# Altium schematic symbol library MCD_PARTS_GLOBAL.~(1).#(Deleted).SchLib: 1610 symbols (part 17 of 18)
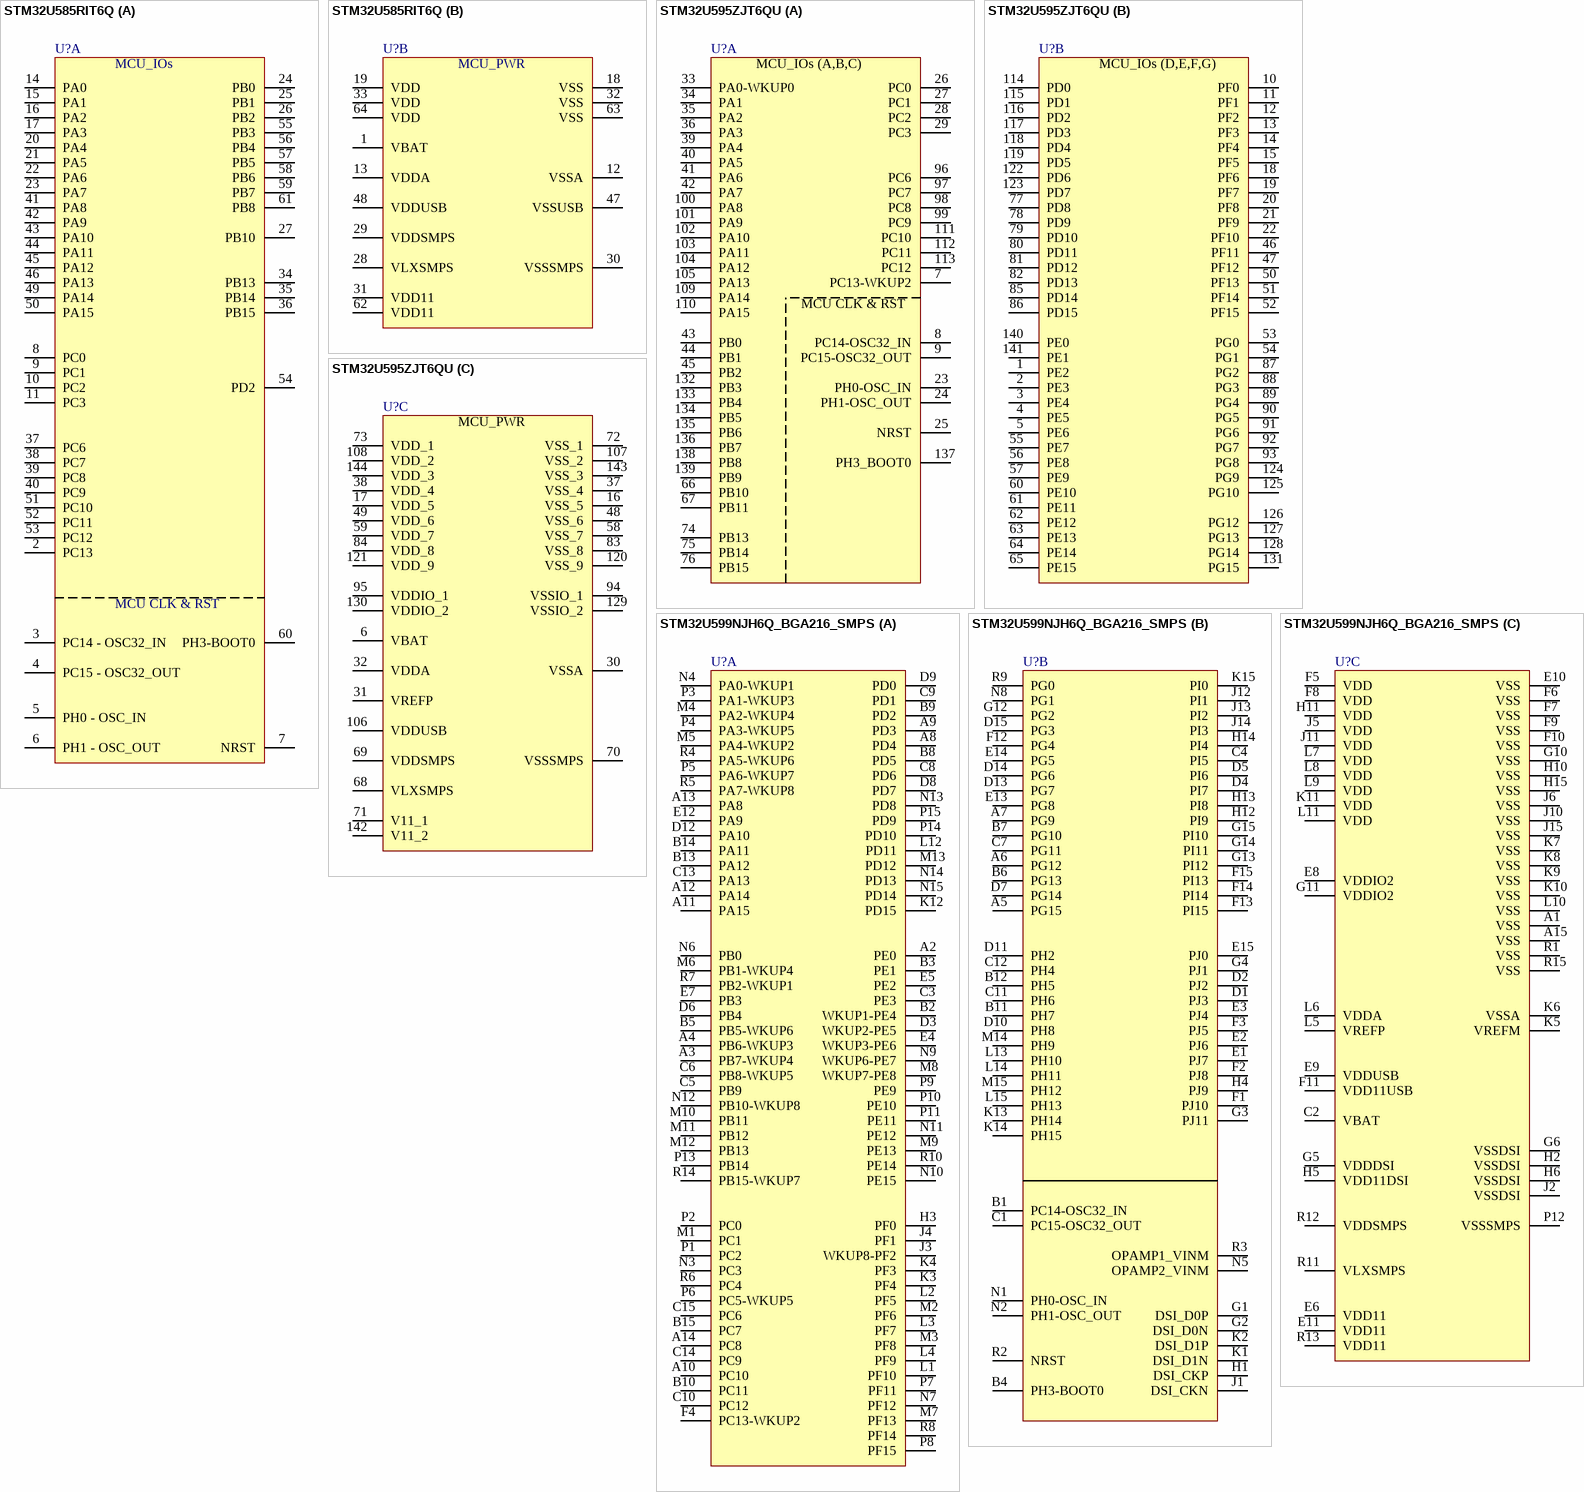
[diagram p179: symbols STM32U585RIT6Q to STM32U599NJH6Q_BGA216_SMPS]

## STM32U599NJH6Q_BGA216_SMPS
designator U?
part A pins: A2 PE0, A3 PB7-WKUP4, A4 PB6-WKUP3, A8 PD4, A9 PD3, A10 PC10, A11 PA15, A12 PA14, A13 PA8, A14 PC8, B2 WKUP1-PE4, B3 PE1, B5 PB5-WKUP6, B8 PD5, B9 PD2, B10 PC11, B13 PA12, B14 PA11, B15 PC7, C3 PE3, C5 PB9, C6 PB8-WKUP5, C8 PD6, C9 PD1, C10 PC12, C13 PA13, C14 PC9, C15 PC6, D3 WKUP2-PE5, D6 PB4, D8 PD7, D9 PD0, D12 PA10, E4 WKUP3-PE6, E5 PE2, E7 PB3, E12 PA9, F4 PC13-WKUP2, H3 PF0, J3 WKUP8-PF2, J4 PF1, K3 PF4, K4 PF3, K12 PD15, L1 PF10, L2 PF5, L3 PF7, L4 PF9, L12 PD11, M1 PC1, M2 PF6, M3 PF8, M4 PA2-WKUP4, M5 PA4-WKUP2, M6 PB1-WKUP4, M7 PF13, M8 WKUP7-PE8, M9 PE13, M10 PB11, M11 PB12, M12 PB13, M13 PD12, N3 PC3, N4 PA0-WKUP1, N6 PB0, N7 PF12, N9 WKUP6-PE7, N10 PE15, N11 PE12, N12 PB10-WKUP8, N13 PD8, N14 PD13, N15 PD14, P1 PC2, P2 PC0, P3 PA1-WKUP3, P4 PA3-WKUP5, P5 PA6-WKUP7, P6 PC5-WKUP5, P7 PF11, P8 PF15, P9 PE9, P10 PE10, P11 PE11, P13 PB14, P14 PD10, P15 PD9, R4 PA5-WKUP6, R5 PA7-WKUP8, R6 PC4, R7 PB2-WKUP1, R8 PF14, R10 PE14, R14 PB15-WKUP7
part B pins: A5 PG15, A6 PG12, A7 PG9, B1 PC14-OSC32_IN, B4 PH3-BOOT0, B6 PG13, B7 PG10, B11 PH7, B12 PH5, C1 PC15-OSC32_OUT, C4 PI5, C7 PG11, C11 PH6, C12 PH4, D1 PJ3, D2 PJ2, D4 PI7, D5 PI6, D7 PG14, D10 PH8, D11 PH2, D13 PG7, D14 PG6, D15 PG3, E1 PJ7, E2 PJ6, E3 PJ4, E13 PG8, E14 PG5, E15 PJ0, F1 PJ10, F2 PJ8, F3 PJ5, F12 PG4, F13 PI15, F14 PI14, F15 PI13, G1 DSI_D0P, G2 DSI_D0N, G3 PJ11, G4 PJ1, G12 PG2, G13 PI12, G14 PI11, G15 PI10, H1 DSI_CKP, H4 PJ9, H12 PI9, H13 PI8, H14 PI4, J1 DSI_CKN, J12 PI1, J13 PI2, J14 PI3, K1 DSI_D1N, K2 DSI_D1P, K13 PH14, K14 PH15, K15 PI0, L13 PH10, L14 PH11, L15 PH13, M14 PH9, M15 PH12, N1 PH0-OSC_IN, N2 PH1-OSC_OUT, N5 OPAMP2_VINM, N8 PG1, R2 NRST, R3 OPAMP1_VINM, R9 PG0
part C pins: A1 VSS, A15 VSS, C2 VBAT, E6 VDD11, E8 VDDIO2, E9 VDDUSB, E10 VSS, E11 VDD11, F5 VDD, F6 VSS, F7 VSS, F8 VDD, F9 VSS, F10 VSS, F11 VDD11USB, G5 VDDDSI, G6 VSSDSI, G10 VSS, G11 VDDIO2, H2 VSSDSI, H5 VDD11DSI, H6 VSSDSI, H10 VSS, H11 VDD, H15 VSS, J2 VSSDSI, J5 VDD, J6 VSS, J10 VSS, J11 VDD, J15 VSS, K5 VREFM, K6 VSSA, K7 VSS, K8 VSS, K9 VSS, K10 VSS, K11 VDD, L5 VREFP, L6 VDDA, L7 VDD, L8 VDD, L9 VDD, L10 VSS, L11 VDD, P12 VSSSMPS, R1 VSS, R11 VLXSMPS, R12 VDDSMPS, R13 VDD11, R15 VSS

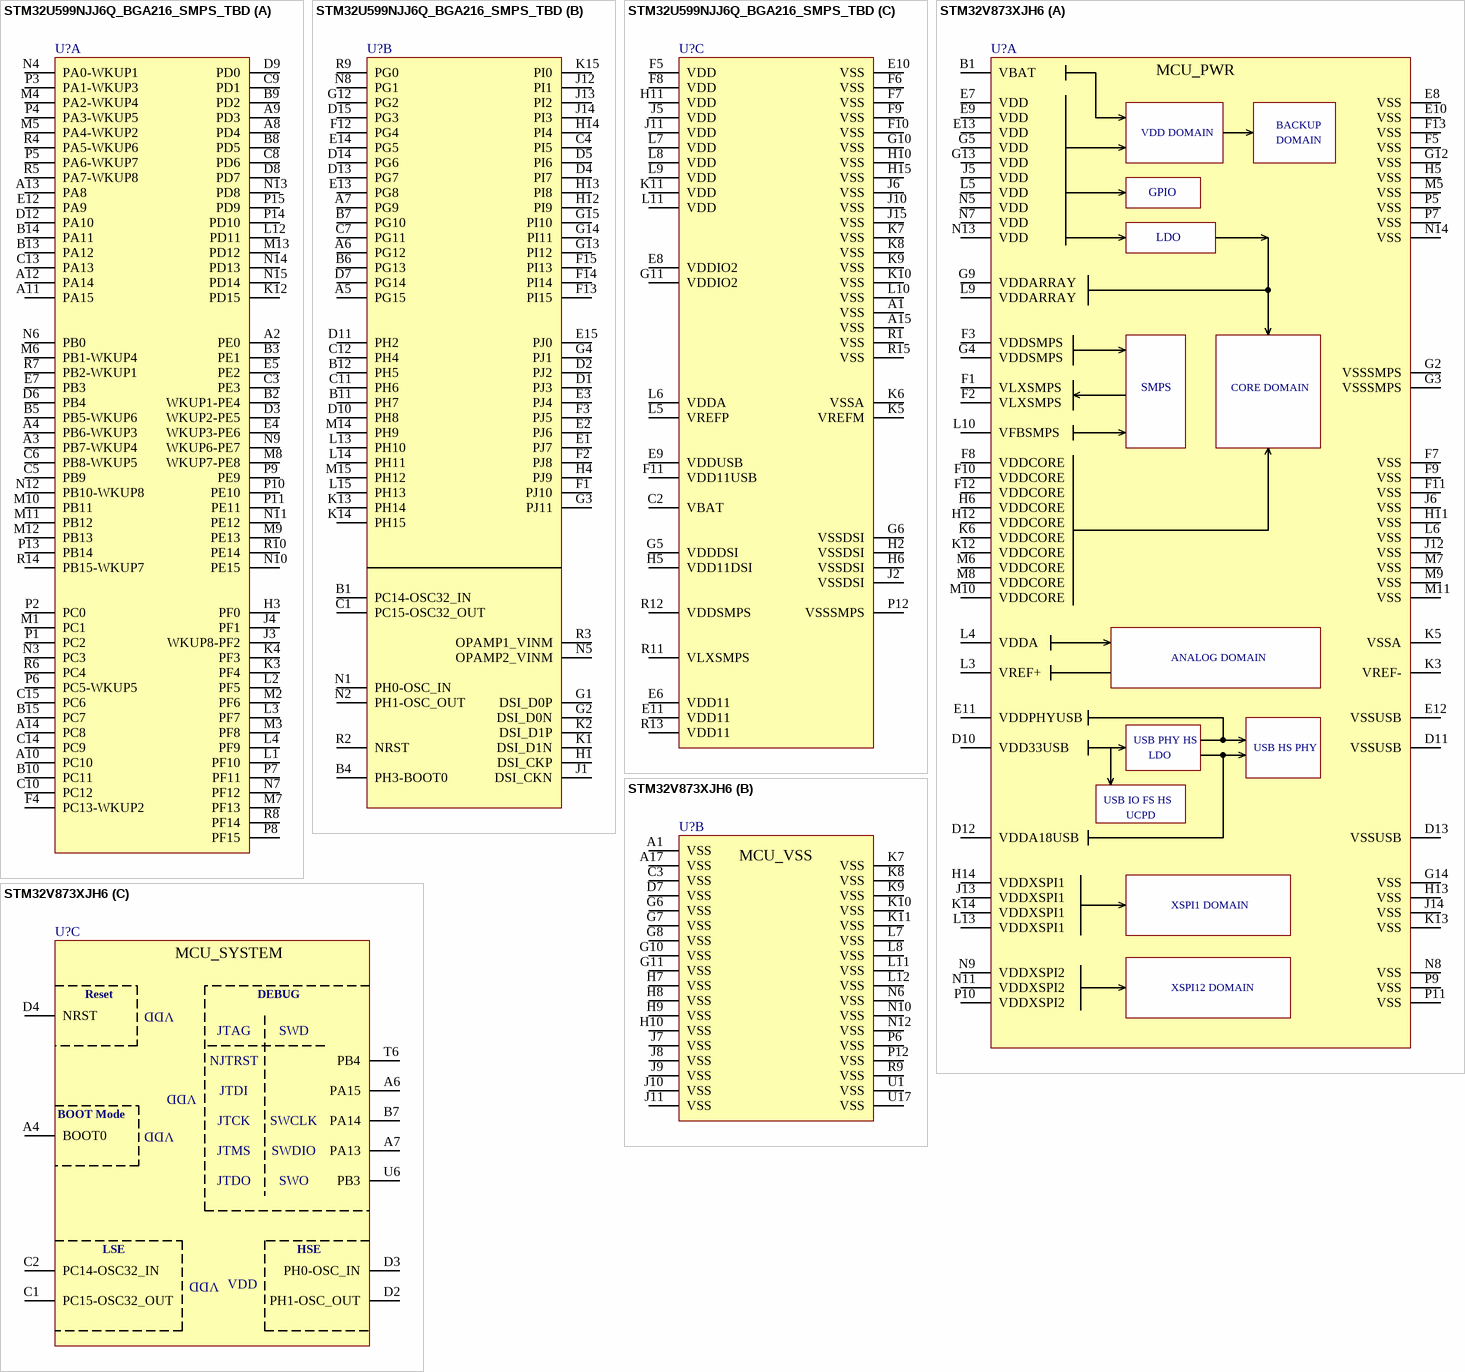
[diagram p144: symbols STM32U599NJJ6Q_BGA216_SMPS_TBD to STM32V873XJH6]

## STM32U599NJJ6Q_BGA216_SMPS_TBD
designator U?
part A pins: A2 PE0, A3 PB7-WKUP4, A4 PB6-WKUP3, A8 PD4, A9 PD3, A10 PC10, A11 PA15, A12 PA14, A13 PA8, A14 PC8, B2 WKUP1-PE4, B3 PE1, B5 PB5-WKUP6, B8 PD5, B9 PD2, B10 PC11, B13 PA12, B14 PA11, B15 PC7, C3 PE3, C5 PB9, C6 PB8-WKUP5, C8 PD6, C9 PD1, C10 PC12, C13 PA13, C14 PC9, C15 PC6, D3 WKUP2-PE5, D6 PB4, D8 PD7, D9 PD0, D12 PA10, E4 WKUP3-PE6, E5 PE2, E7 PB3, E12 PA9, F4 PC13-WKUP2, H3 PF0, J3 WKUP8-PF2, J4 PF1, K3 PF4, K4 PF3, K12 PD15, L1 PF10, L2 PF5, L3 PF7, L4 PF9, L12 PD11, M1 PC1, M2 PF6, M3 PF8, M4 PA2-WKUP4, M5 PA4-WKUP2, M6 PB1-WKUP4, M7 PF13, M8 WKUP7-PE8, M9 PE13, M10 PB11, M11 PB12, M12 PB13, M13 PD12, N3 PC3, N4 PA0-WKUP1, N6 PB0, N7 PF12, N9 WKUP6-PE7, N10 PE15, N11 PE12, N12 PB10-WKUP8, N13 PD8, N14 PD13, N15 PD14, P1 PC2, P2 PC0, P3 PA1-WKUP3, P4 PA3-WKUP5, P5 PA6-WKUP7, P6 PC5-WKUP5, P7 PF11, P8 PF15, P9 PE9, P10 PE10, P11 PE11, P13 PB14, P14 PD10, P15 PD9, R4 PA5-WKUP6, R5 PA7-WKUP8, R6 PC4, R7 PB2-WKUP1, R8 PF14, R10 PE14, R14 PB15-WKUP7
part B pins: A5 PG15, A6 PG12, A7 PG9, B1 PC14-OSC32_IN, B4 PH3-BOOT0, B6 PG13, B7 PG10, B11 PH7, B12 PH5, C1 PC15-OSC32_OUT, C4 PI5, C7 PG11, C11 PH6, C12 PH4, D1 PJ3, D2 PJ2, D4 PI7, D5 PI6, D7 PG14, D10 PH8, D11 PH2, D13 PG7, D14 PG6, D15 PG3, E1 PJ7, E2 PJ6, E3 PJ4, E13 PG8, E14 PG5, E15 PJ0, F1 PJ10, F2 PJ8, F3 PJ5, F12 PG4, F13 PI15, F14 PI14, F15 PI13, G1 DSI_D0P, G2 DSI_D0N, G3 PJ11, G4 PJ1, G12 PG2, G13 PI12, G14 PI11, G15 PI10, H1 DSI_CKP, H4 PJ9, H12 PI9, H13 PI8, H14 PI4, J1 DSI_CKN, J12 PI1, J13 PI2, J14 PI3, K1 DSI_D1N, K2 DSI_D1P, K13 PH14, K14 PH15, K15 PI0, L13 PH10, L14 PH11, L15 PH13, M14 PH9, M15 PH12, N1 PH0-OSC_IN, N2 PH1-OSC_OUT, N5 OPAMP2_VINM, N8 PG1, R2 NRST, R3 OPAMP1_VINM, R9 PG0
part C pins: A1 VSS, A15 VSS, C2 VBAT, E6 VDD11, E8 VDDIO2, E9 VDDUSB, E10 VSS, E11 VDD11, F5 VDD, F6 VSS, F7 VSS, F8 VDD, F9 VSS, F10 VSS, F11 VDD11USB, G5 VDDDSI, G6 VSSDSI, G10 VSS, G11 VDDIO2, H2 VSSDSI, H5 VDD11DSI, H6 VSSDSI, H10 VSS, H11 VDD, H15 VSS, J2 VSSDSI, J5 VDD, J6 VSS, J10 VSS, J11 VDD, J15 VSS, K5 VREFM, K6 VSSA, K7 VSS, K8 VSS, K9 VSS, K10 VSS, K11 VDD, L5 VREFP, L6 VDDA, L7 VDD, L8 VDD, L9 VDD, L10 VSS, L11 VDD, P12 VSSSMPS, R1 VSS, R11 VLXSMPS, R12 VDDSMPS, R13 VDD11, R15 VSS

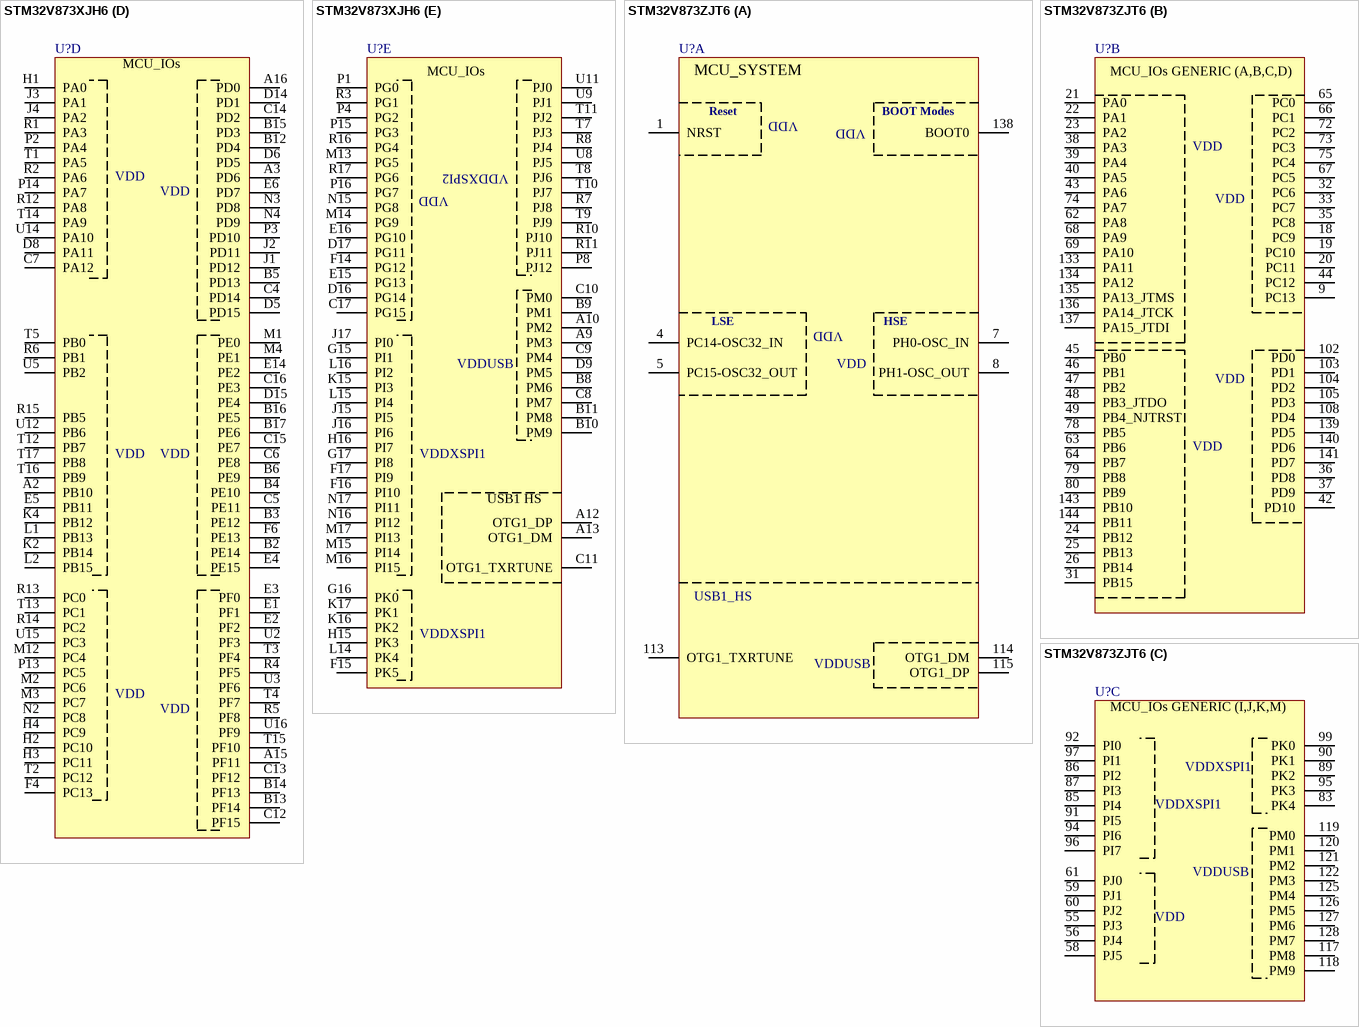
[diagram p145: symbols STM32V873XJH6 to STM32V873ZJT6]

## STM32V873XJH6
designator U?
part A pins: B1 VBAT, D10 VDD33USB, D11 VSSUSB, D12 VDDA18USB, D13 VSSUSB, E7 VDD, E8 VSS, E9 VDD, E10 VSS, E11 VDDPHYUSB, E12 VSSUSB, E13 VDD, F1 VLXSMPS, F2 VLXSMPS, F3 VDDSMPS, F5 VSS, F7 VSS, F8 VDDCORE, F9 VSS, F10 VDDCORE, F11 VSS, F12 VDDCORE, F13 VSS, G2 VSSSMPS, G3 VSSSMPS, G4 VDDSMPS, G5 VDD, G9 VDDARRAY, G12 VSS, G13 VDD, G14 VSS, H5 VSS, H6 VDDCORE, H11 VSS, H12 VDDCORE, H13 VSS, H14 VDDXSPI1, J5 VDD, J6 VSS, J12 VSS, J13 VDDXSPI1, J14 VSS, K3 VREF-, K5 VSSA, K6 VDDCORE, K12 VDDCORE, K13 VSS, K14 VDDXSPI1, L3 VREF+, L4 VDDA, L5 VDD, L6 VSS, L9 VDDARRAY, L10 VFBSMPS, L13 VDDXSPI1, M5 VSS, M6 VDDCORE, M7 VSS, M8 VDDCORE, M9 VSS, M10 VDDCORE, M11 VSS, N5 VDD, N7 VDD, N8 VSS, N9 VDDXSPI2, N11 VDDXSPI2, N13 VDD, N14 VSS, P5 VSS, P7 VSS, P9 VSS, P10 VDDXSPI2, P11 VSS
part B pins: A1 VSS, A17 VSS, C3 VSS, D7 VSS, G6 VSS, G7 VSS, G8 VSS, G10 VSS, G11 VSS, H7 VSS, H8 VSS, H9 VSS, H10 VSS, J7 VSS, J8 VSS, J9 VSS, J10 VSS, J11 VSS, K7 VSS, K8 VSS, K9 VSS, K10 VSS, K11 VSS, L7 VSS, L8 VSS, L11 VSS, L12 VSS, N6 VSS, N10 VSS, N12 VSS, P6 VSS, P12 VSS, R9 VSS, U1 VSS, U17 VSS
part C pins: A4 BOOT0, A6 PA15, A7 PA13, B7 PA14, C1 PC15-OSC32_OUT, C2 PC14-OSC32_IN, D2 PH1-OSC_OUT, D3 PH0-OSC_IN, D4 NRST, T6 PB4, U6 PB3
part D pins: A2 PB10, A3 PD6, A15 PF11, A16 PD0, B2 PE14, B3 PE12, B4 PE10, B5 PD13, B6 PE9, B12 PD4, B13 PF14, B14 PF13, B15 PD3, B16 PE5, B17 PE6, C4 PD14, C5 PE11, C6 PE8, C7 PA12, C12 PF15, C13 PF12, C14 PD2, C15 PE7, C16 PE3, D5 PD15, D6 PD5, D8 PA11, D14 PD1, D15 PE4, E1 PF1, E2 PF2, E3 PF0, E4 PE15, E5 PB11, E6 PD7, E14 PE2, F4 PC13, F6 PE13, H1 PA0, H2 PC10, H3 PC11, H4 PC9, J1 PD12, J2 PD11, J3 PA1, J4 PA2, K2 PB14, K4 PB12, L1 PB13, L2 PB15, M1 PE0, M2 PC6, M3 PC7, M4 PE1, M12 PC4, N2 PC8, N3 PD8, N4 PD9, P2 PA4, P3 PD10, P13 PC5, P14 PA7, R1 PA3, R2 PA6, R4 PF5, R5 PF8, R6 PB1, R12 PA8, R13 PC0, R14 PC2, R15 PB5, T1 PA5, T2 PC12, T3 PF4, T4 PF7, T5 PB0, T12 PB7, T13 PC1, T14 PA9, T15 PF10, T16 PB9, T17 PB8, U2 PF3, U3 PF6, U5 PB2, U12 PB6, U14 PA10, U15 PC3, U16 PF9
part E pins: A9 PM3, A10 PM2, A12 OTG1_DP, A13 OTG1_DM, B8 PM6, B9 PM1, B10 PM9, B11 PM8, C8 PM7, C9 PM4, C10 PM0, C11 OTG1_TXRTUNE, C17 PG15, D9 PM5, D16 PG14, D17 PG11, E15 PG13, E16 PG10, F14 PG12, F15 PK5, F16 PI10, F17 PI9, G15 PI1, G16 PK0, G17 PI8, H15 PK3, H16 PI7, J15 PI5, J16 PI6, J17 PI0, K15 PI3, K16 PK2, K17 PK1, L14 PK4, L15 PI4, L16 PI2, M13 PG5, M14 PG9, M15 PI14, M16 PI15, M17 PI13, N15 PG8, N16 PI12, N17 PI11, P1 PG0, P4 PG2, P8 PJ12, P15 PG3, P16 PG7, R3 PG1, R7 PJ8, R8 PJ4, R10 PJ10, R11 PJ11, R16 PG4, R17 PG6, T7 PJ3, T8 PJ6, T9 PJ9, T10 PJ7, T11 PJ2, U8 PJ5, U9 PJ1, U11 PJ0
1 alternate drawing of the same symbol

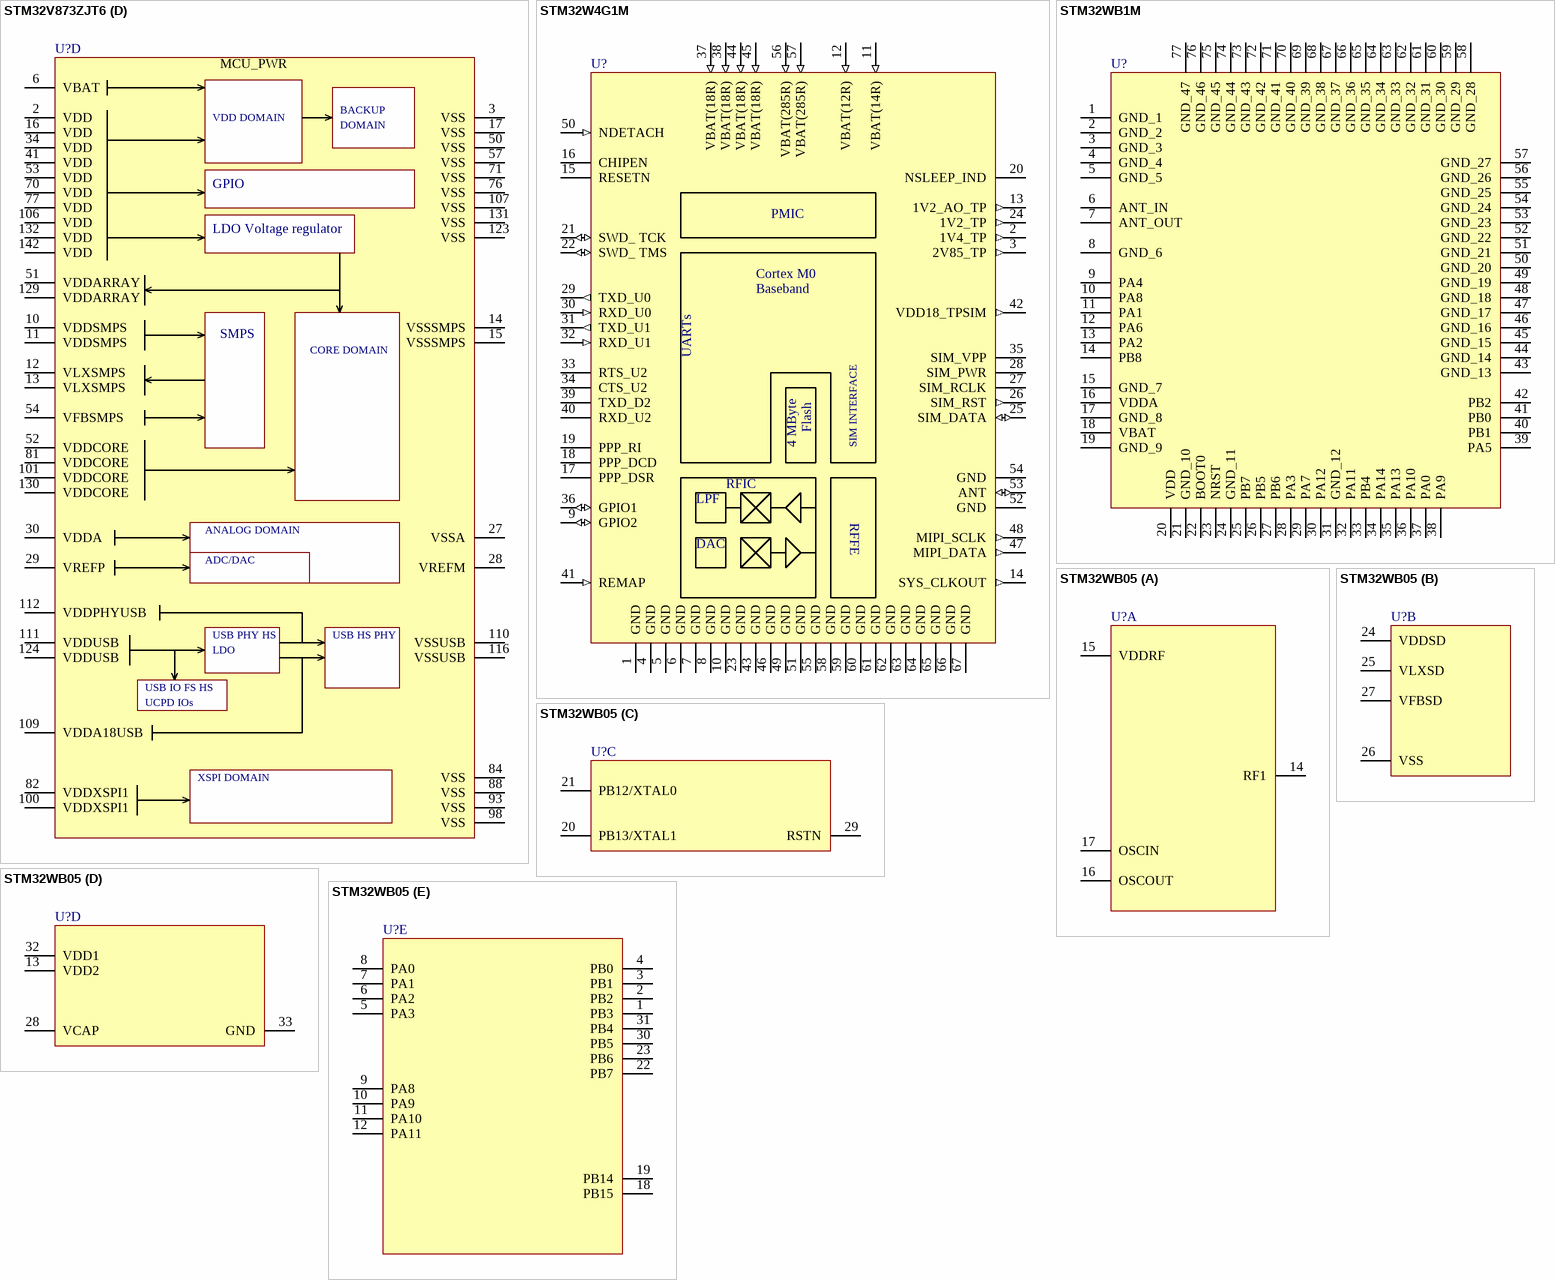
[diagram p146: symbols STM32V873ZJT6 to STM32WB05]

## STM32V873ZJT6
designator U?
part A pins: 1 NRST, 4 PC14-OSC32_IN, 5 PC15-OSC32_OUT, 7 PH0-OSC_IN, 8 PH1-OSC_OUT, 113 OTG1_TXRTUNE, 114 OTG1_DM, 115 OTG1_DP, 138 BOOT0
part B pins: 9 PC13, 18 PC9, 19 PC10, 20 PC11, 21 PA0, 22 PA1, 23 PA2, 24 PB12, 25 PB13, 26 PB14, 31 PB15, 32 PC6, 33 PC7, 35 PC8, 36 PD8, 37 PD9, 38 PA3, 39 PA4, 40 PA5, 42 PD10, 43 PA6, 44 PC12, 45 PB0, 46 PB1, 47 PB2, 48 PB3_JTDO, 49 PB4_NJTRST, 62 PA8, 63 PB6, 64 PB7, 65 PC0, 66 PC1, 67 PC5, 68 PA9, 69 PA10, 72 PC2, 73 PC3, 74 PA7, 75 PC4, 78 PB5, 79 PB8, 80 PB9, 102 PD0, 103 PD1, 104 PD2, 105 PD3, 108 PD4, 133 PA11, 134 PA12, 135 PA13_JTMS, 136 PA14_JTCK, 137 PA15_JTDI, 139 PD5, 140 PD6, 141 PD7, 143 PB10, 144 PB11
part C pins: 55 PJ3, 56 PJ4, 58 PJ5, 59 PJ1, 60 PJ2, 61 PJ0, 83 PK4, 85 PI4, 86 PI2, 87 PI3, 89 PK2, 90 PK1, 91 PI5, 92 PI0, 94 PI6, 95 PK3, 96 PI7, 97 PI1, 99 PK0, 117 PM8, 118 PM9, 119 PM0, 120 PM1, 121 PM2, 122 PM3, 125 PM4, 126 PM5, 127 PM6, 128 PM7
part D pins: 2 VDD, 3 VSS, 6 VBAT, 10 VDDSMPS, 11 VDDSMPS, 12 VLXSMPS, 13 VLXSMPS, 14 VSSSMPS, 15 VSSSMPS, 16 VDD, 17 VSS, 27 VSSA, 28 VREFM, 29 VREFP, 30 VDDA, 34 VDD, 41 VDD, 50 VSS, 51 VDDARRAY, 52 VDDCORE, 53 VDD, 54 VFBSMPS, 57 VSS, 70 VDD, 71 VSS, 76 VSS, 77 VDD, 81 VDDCORE, 82 VDDXSPI1, 84 VSS, 88 VSS, 93 VSS, 98 VSS, 100 VDDXSPI1, 101 VDDCORE, 106 VDD, 107 VSS, 109 VDDA18USB, 110 VSSUSB, 111 VDDUSB, 112 VDDPHYUSB, 116 VSSUSB, 123 VSS, 124 VDDUSB, 129 VDDARRAY, 130 VDDCORE, 131 VSS, 132 VDD, 142 VDD

## STM32W4G1M
designator U?
pins: 1 GND, 2 1V4_TP (out), 3 2V85_TP (out), 4 GND, 5 GND, 6 GND, 7 GND, 8 GND, 9 GPIO2 (io), 10 GND, 11 VBAT(14R) (in), 12 VBAT(12R) (in), 13 1V2_AO_TP (out), 14 SYS_CLKOUT (out), 15 RESETN, 16 CHIPEN, 17 PPP_DSR, 18 PPP_DCD, 19 PPP_RI, 20 NSLEEP_IND, 21 SWD_ TCK (io), 22 SWD_ TMS (io), 23 GND, 24 1V2_TP (out), 25 SIM_DATA (io), 26 SIM_RST (out), 27 SIM_RCLK, 28 SIM_PWR, 29 TXD_U0 (out), 30 RXD_U0 (in), 31 TXD_U1 (out), 32 RXD_U1 (in), 33 RTS_U2, 34 CTS_U2, 35 SIM_VPP, 36 GPIO1 (io), 37 VBAT(18R) (in), 38 VBAT(18R) (in), 39 TXD_D2, 40 RXD_U2, 41 REMAP (in), 42 VDD18_TPSIM (out), 43 GND, 44 VBAT(18R) (in), 45 VBAT(18R) (in), 46 GND, 47 MIPI_DATA (out), 48 MIPI_SCLK (out), 49 GND, 50 NDETACH (in), 51 GND, 52 GND (power), 53 ANT (io) "Antenna connector", 54 GND (power), 55 GND, 56 VBAT(285R) (in), 57 VBAT(285R) (in), 58 GND, 59 GND, 60 GND, 61 GND, 62 GND, 63 GND, 64 GND, 65 GND, 66 GND, 67 GND

## STM32WB1M
designator U?
pins: 1 GND_1, 2 GND_2, 3 GND_3, 4 GND_4, 5 GND_5, 6 ANT_IN, 7 ANT_OUT, 8 GND_6, 9 PA4, 10 PA8, 11 PA1, 12 PA6, 13 PA2, 14 PB8, 15 GND_7, 16 VDDA, 17 GND_8, 18 VBAT, 19 GND_9, 20 VDD, 21 GND_10, 22 BOOT0, 23 NRST, 24 GND_11, 25 PB7, 26 PB5, 27 PB6, 28 PA3, 29 PA7, 30 PA12, 31 GND_12, 32 PA11, 33 PB4, 34 PA14, 35 PA13, 36 PA10, 37 PA0, 38 PA9, 39 PA5, 40 PB1, 41 PB0, 42 PB2, 43 GND_13, 44 GND_14, 45 GND_15, 46 GND_16, 47 GND_17, 48 GND_18, 49 GND_19, 50 GND_20, 51 GND_21, 52 GND_22, 53 GND_23, 54 GND_24, 55 GND_25, 56 GND_26, 57 GND_27, 58 GND_28, 59 GND_29, 60 GND_30, 61 GND_31, 62 GND_32, 63 GND_33, 64 GND_34, 65 GND_35, 66 GND_36, 67 GND_37, 68 GND_38, 69 GND_39, 70 GND_40, 71 GND_41, 72 GND_42, 73 GND_43, 74 GND_44, 75 GND_45, 76 GND_46, 77 GND_47

## STM32WB05
designator U?
part A pins: 14 RF1, 15 VDDRF, 16 OSCOUT, 17 OSCIN
part B pins: 24 VDDSD, 25 VLXSD, 26 VSS, 27 VFBSD
part C pins: 20 PB13/XTAL1, 21 PB12/XTAL0, 29 RSTN
part D pins: 13 VDD2, 28 VCAP, 32 VDD1, 33 GND
part E pins: 1 PB3, 2 PB2, 3 PB1, 4 PB0, 5 PA3, 6 PA2, 7 PA1, 8 PA0, 9 PA8, 10 PA9, 11 PA10, 12 PA11, 18 PB15, 19 PB14, 22 PB7, 23 PB6, 30 PB5, 31 PB4

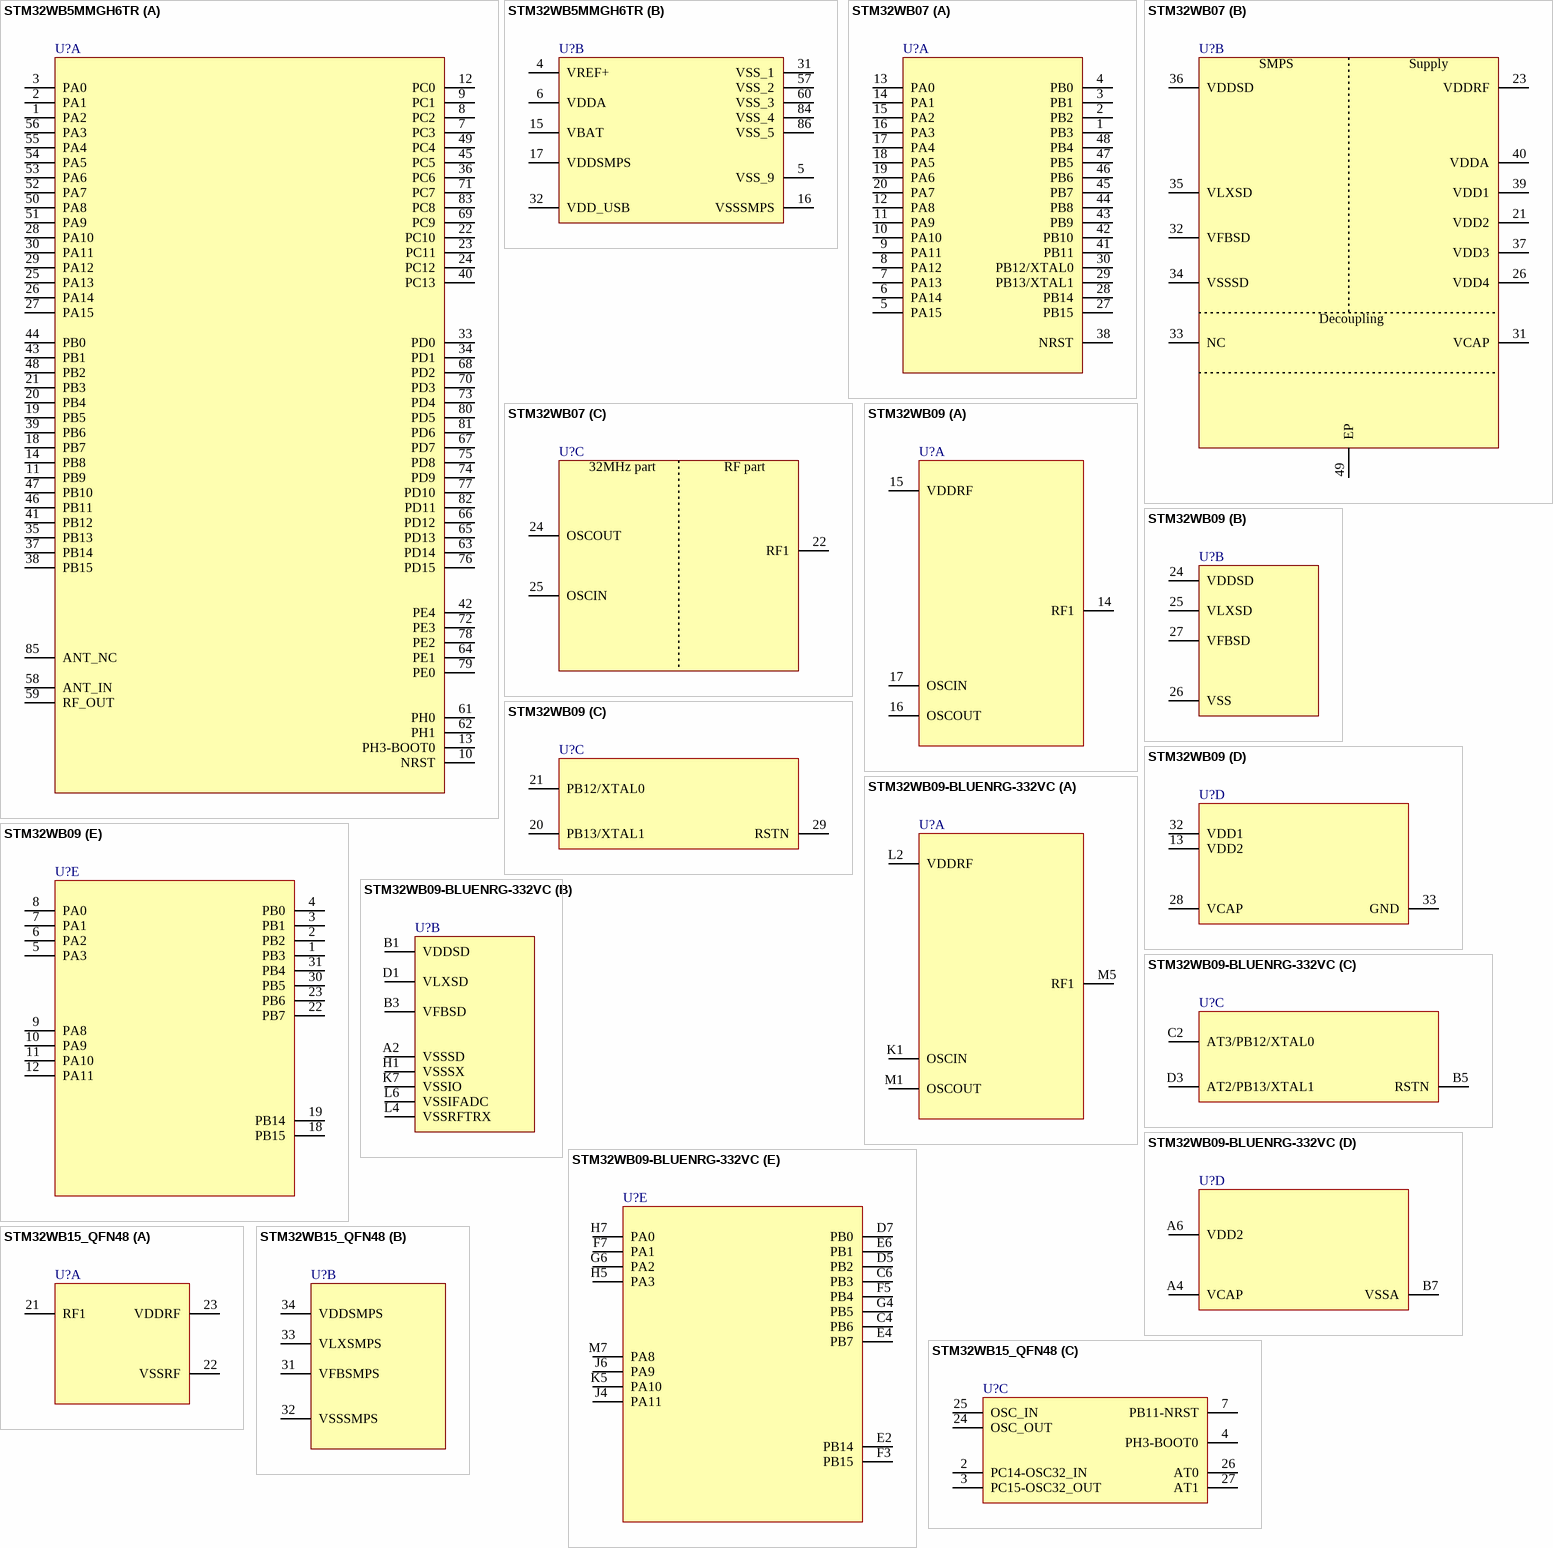
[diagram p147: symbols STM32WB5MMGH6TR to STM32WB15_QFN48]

## STM32WB5MMGH6TR
designator U?
part A pins: 1 PA2, 2 PA1, 3 PA0, 7 PC3, 8 PC2, 9 PC1, 10 NRST, 11 PB9, 12 PC0, 13 PH3-BOOT0, 14 PB8, 18 PB7, 19 PB5, 20 PB4, 21 PB3, 22 PC10, 23 PC11, 24 PC12, 25 PA13, 26 PA14, 27 PA15, 28 PA10, 29 PA12, 30 PA11, 33 PD0, 34 PD1, 35 PB13, 36 PC6, 37 PB14, 38 PB15, 39 PB6, 40 PC13, 41 PB12, 42 PE4, 43 PB1, 44 PB0, 45 PC5, 46 PB11, 47 PB10, 48 PB2, 49 PC4, 50 PA8, 51 PA9, 52 PA7, 53 PA6, 54 PA5, 55 PA4, 56 PA3, 58 ANT_IN, 59 RF_OUT, 61 PH0, 62 PH1, 63 PD14, 64 PE1, 65 PD13, 66 PD12, 67 PD7, 68 PD2, 69 PC9, 70 PD3, 71 PC7, 72 PE3, 73 PD4, 74 PD9, 75 PD8, 76 PD15, 77 PD10, 78 PE2, 79 PE0, 80 PD5, 81 PD6, 82 PD11, 83 PC8, 85 ANT_NC
part B pins: 4 VREF+, 5 VSS_9, 6 VDDA, 15 VBAT, 16 VSSSMPS, 17 VDDSMPS, 31 VSS_1, 32 VDD_USB, 57 VSS_2, 60 VSS_3, 84 VSS_4, 86 VSS_5

## STM32WB07
designator U?
part A pins: 1 PB3, 2 PB2, 3 PB1, 4 PB0, 5 PA15, 6 PA14, 7 PA13, 8 PA12, 9 PA11, 10 PA10, 11 PA9, 12 PA8, 13 PA0, 14 PA1, 15 PA2, 16 PA3, 17 PA4, 18 PA5, 19 PA6, 20 PA7, 27 PB15, 28 PB14, 29 PB13/XTAL1, 30 PB12/XTAL0, 38 NRST, 41 PB11, 42 PB10, 43 PB9, 44 PB8, 45 PB7, 46 PB6, 47 PB5, 48 PB4
part B pins: 21 VDD2, 23 VDDRF, 26 VDD4, 31 VCAP, 32 VFBSD, 33 NC, 34 VSSSD, 35 VLXSD, 36 VDDSD, 37 VDD3, 39 VDD1, 40 VDDA, 49 EP
part C pins: 22 RF1, 24 OSCOUT, 25 OSCIN

## STM32WB09
designator U?
part A pins: 14 RF1, 15 VDDRF, 16 OSCOUT, 17 OSCIN
part B pins: 24 VDDSD, 25 VLXSD, 26 VSS, 27 VFBSD
part C pins: 20 PB13/XTAL1, 21 PB12/XTAL0, 29 RSTN
part D pins: 13 VDD2, 28 VCAP, 32 VDD1, 33 GND
part E pins: 1 PB3, 2 PB2, 3 PB1, 4 PB0, 5 PA3, 6 PA2, 7 PA1, 8 PA0, 9 PA8, 10 PA9, 11 PA10, 12 PA11, 18 PB15, 19 PB14, 22 PB7, 23 PB6, 30 PB5, 31 PB4

## STM32WB09-BLUENRG-332VC
designator U?
part A pins: K1 OSCIN, L2 VDDRF, M1 OSCOUT, M5 RF1
part B pins: A2 VSSSD, B1 VDDSD, B3 VFBSD, D1 VLXSD, H1 VSSSX, K7 VSSIO, L4 VSSRFTRX, L6 VSSIFADC
part C pins: B5 RSTN, C2 AT3/PB12/XTAL0, D3 AT2/PB13/XTAL1
part D pins: A4 VCAP, A6 VDD2, B7 VSSA
part E pins: C4 PB6, C6 PB3, D5 PB2, D7 PB0, E2 PB14, E4 PB7, E6 PB1, F3 PB15, F5 PB4, F7 PA1, G4 PB5, G6 PA2, H5 PA3, H7 PA0, J4 PA11, J6 PA9, K5 PA10, M7 PA8

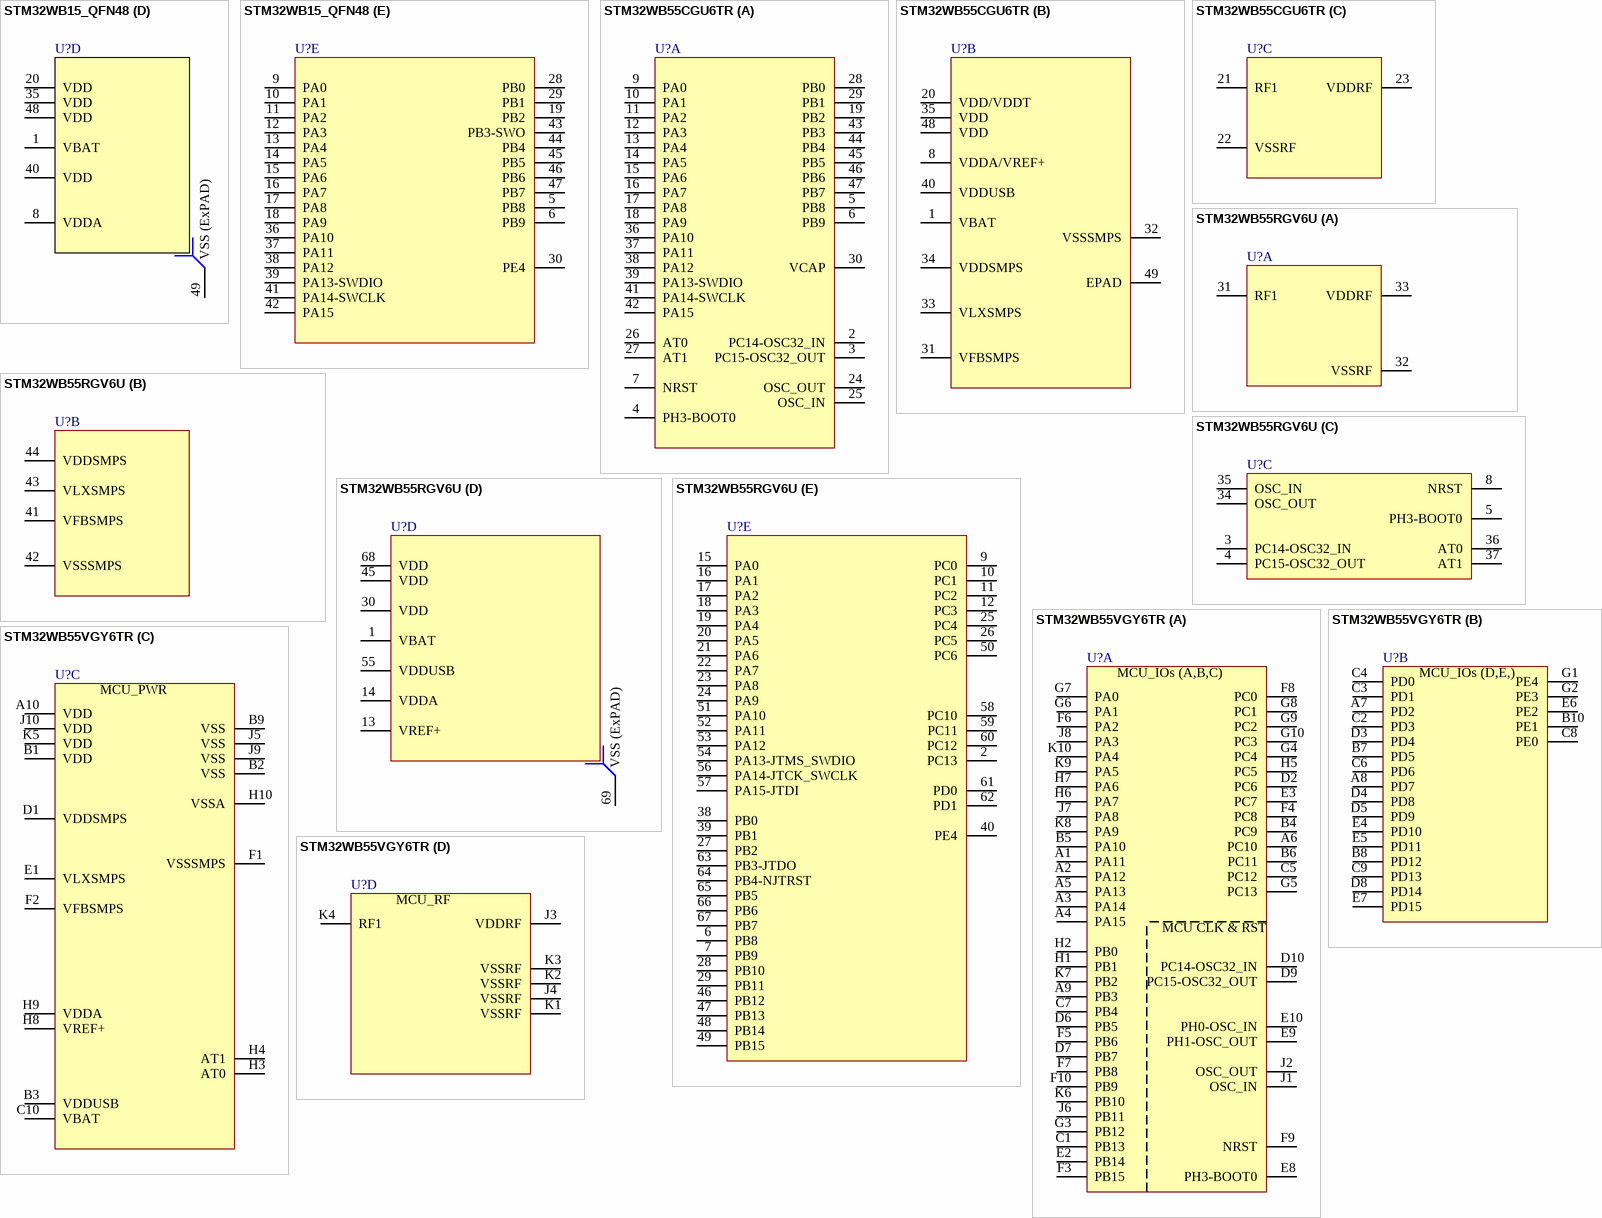
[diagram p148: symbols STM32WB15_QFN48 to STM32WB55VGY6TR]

## STM32WB15_QFN48
designator U?
part A pins: 21 RF1, 22 VSSRF, 23 VDDRF
part B pins: 31 VFBSMPS, 32 VSSSMPS, 33 VLXSMPS, 34 VDDSMPS
part C pins: 2 PC14-OSC32_IN, 3 PC15-OSC32_OUT, 4 PH3-BOOT0, 7 PB11-NRST, 24 OSC_OUT, 25 OSC_IN, 26 AT0, 27 AT1
part D pins: 1 VBAT, 8 VDDA, 20 VDD, 35 VDD, 40 VDD, 48 VDD, 49 VSS (ExPAD)
part E pins: 5 PB8, 6 PB9, 9 PA0, 10 PA1, 11 PA2, 12 PA3, 13 PA4, 14 PA5, 15 PA6, 16 PA7, 17 PA8, 18 PA9, 19 PB2, 28 PB0, 29 PB1, 30 PE4, 36 PA10, 37 PA11, 38 PA12, 39 PA13-SWDIO, 41 PA14-SWCLK, 42 PA15, 43 PB3-SWO, 44 PB4, 45 PB5, 46 PB6, 47 PB7

## STM32WB55CGU6TR
designator U?
part A pins: 2 PC14-OSC32_IN, 3 PC15-OSC32_OUT, 4 PH3-BOOT0, 5 PB8, 6 PB9, 7 NRST, 9 PA0, 10 PA1, 11 PA2, 12 PA3, 13 PA4, 14 PA5, 15 PA6, 16 PA7, 17 PA8, 18 PA9, 19 PB2, 24 OSC_OUT, 25 OSC_IN, 26 AT0, 27 AT1, 28 PB0, 29 PB1, 30 VCAP, 36 PA10, 37 PA11, 38 PA12, 39 PA13-SWDIO, 41 PA14-SWCLK, 42 PA15, 43 PB3, 44 PB4, 45 PB5, 46 PB6, 47 PB7
part B pins: 1 VBAT, 8 VDDA/VREF+, 20 VDD/VDDT, 31 VFBSMPS, 32 VSSSMPS, 33 VLXSMPS, 34 VDDSMPS, 35 VDD, 40 VDDUSB, 48 VDD, 49 EPAD
part C pins: 21 RF1, 22 VSSRF, 23 VDDRF

## STM32WB55RGV6U
designator U?
part A pins: 31 RF1, 32 VSSRF, 33 VDDRF
part B pins: 41 VFBSMPS, 42 VSSSMPS, 43 VLXSMPS, 44 VDDSMPS
part C pins: 3 PC14-OSC32_IN, 4 PC15-OSC32_OUT, 5 PH3-BOOT0, 8 NRST, 34 OSC_OUT, 35 OSC_IN, 36 AT0, 37 AT1
part D pins: 1 VBAT, 13 VREF+, 14 VDDA, 30 VDD, 45 VDD, 55 VDDUSB, 68 VDD, 69 VSS (ExPAD)
part E pins: 2 PC13, 6 PB8, 7 PB9, 9 PC0, 10 PC1, 11 PC2, 12 PC3, 15 PA0, 16 PA1, 17 PA2, 18 PA3, 19 PA4, 20 PA5, 21 PA6, 22 PA7, 23 PA8, 24 PA9, 25 PC4, 26 PC5, 27 PB2, 28 PB10, 29 PB11, 38 PB0, 39 PB1, 40 PE4, 46 PB12, 47 PB13, 48 PB14, 49 PB15, 50 PC6, 51 PA10, 52 PA11, 53 PA12, 54 PA13-JTMS_SWDIO, 56 PA14-JTCK_SWCLK, 57 PA15-JTDI, 58 PC10, 59 PC11, 60 PC12, 61 PD0, 62 PD1, 63 PB3-JTDO, 64 PB4-NJTRST, 65 PB5, 66 PB6, 67 PB7

## STM32WB55VGY6TR
designator U?
part A pins: A1 PA11, A2 PA12, A3 PA14, A4 PA15, A5 PA13, A6 PC10, A9 PB3, B4 PC9, B5 PA10, B6 PC11, C1 PB13, C5 PC12, C7 PB4, D2 PC6, D6 PB5, D7 PB7, D9 PC15-OSC32_OUT, D10 PC14-OSC32_IN, E2 PB14, E3 PC7, E8 PH3-BOOT0, E9 PH1-OSC_OUT, E10 PH0-OSC_IN, F3 PB15, F4 PC8, F5 PB6, F6 PA2, F7 PB8, F8 PC0, F9 NRST, F10 PB9, G3 PB12, G4 PC4, G5 PC13, G6 PA1, G7 PA0, G8 PC1, G9 PC2, G10 PC3, H1 PB1, H2 PB0, H5 PC5, H6 PA7, H7 PA6, J1 OSC_IN, J2 OSC_OUT, J6 PB11, J7 PA8, J8 PA3, K6 PB10, K7 PB2, K8 PA9, K9 PA5, K10 PA4
part B pins: A7 PD2, A8 PD7, B7 PD5, B8 PD12, B10 PE1, C2 PD3, C3 PD1, C4 PD0, C6 PD6, C8 PE0, C9 PD13, D3 PD4, D4 PD8, D5 PD9, D8 PD14, E4 PD10, E5 PD11, E6 PE2, E7 PD15, G1 PE4, G2 PE3
part C pins: A10 VDD, B1 VDD, B2 VSS, B3 VDDUSB, B9 VSS, C10 VBAT, D1 VDDSMPS, E1 VLXSMPS, F1 VSSSMPS, F2 VFBSMPS, H3 AT0, H4 AT1, H8 VREF+, H9 VDDA, H10 VSSA, J5 VSS, J9 VSS, J10 VDD, K5 VDD
part D pins: J3 VDDRF, J4 VSSRF, K1 VSSRF, K2 VSSRF, K3 VSSRF, K4 RF1

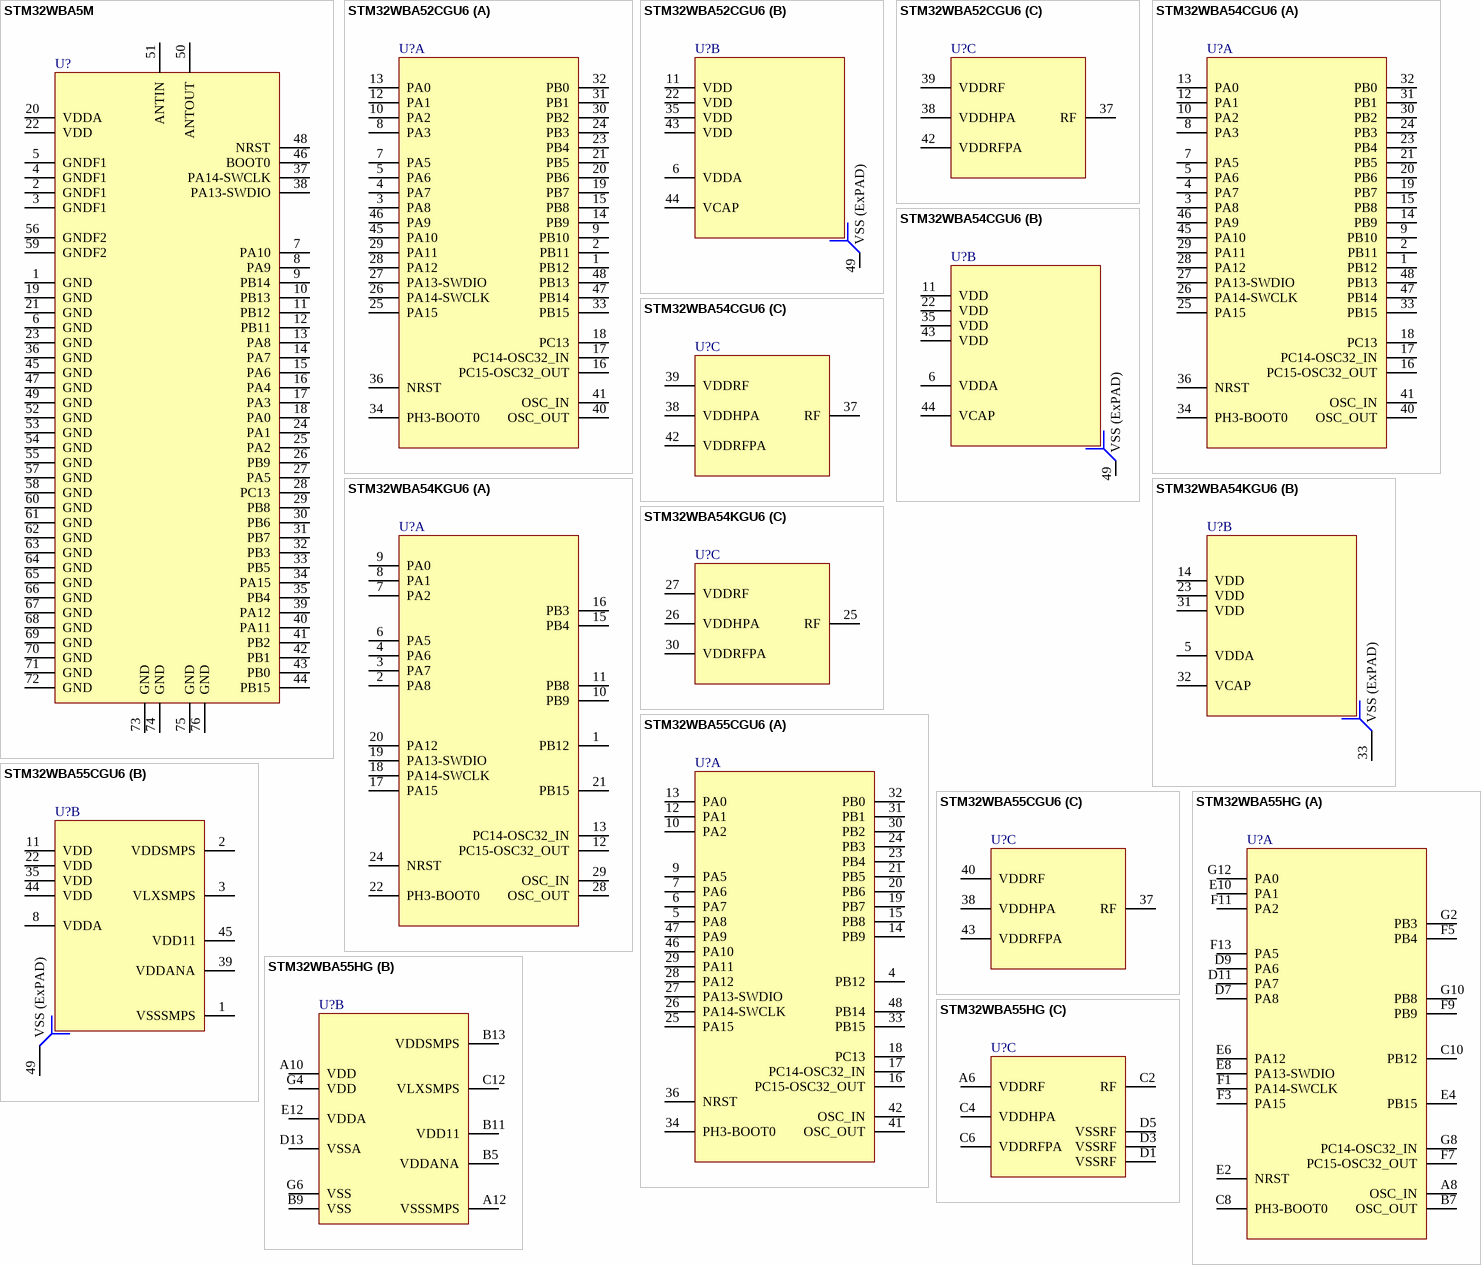
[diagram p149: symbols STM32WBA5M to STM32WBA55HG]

## STM32WBA5M
designator U?
pins: 1 GND, 2 GNDF1, 3 GNDF1, 4 GNDF1, 5 GNDF1, 6 GND, 7 PA10, 8 PA9, 9 PB14, 10 PB13, 11 PB12, 12 PB11, 13 PA8, 14 PA7, 15 PA6, 16 PA4, 17 PA3, 18 PA0, 19 GND, 20 VDDA, 21 GND, 22 VDD, 23 GND, 24 PA1, 25 PA2, 26 PB9, 27 PA5, 28 PC13, 29 PB8, 30 PB6, 31 PB7, 32 PB3, 33 PB5, 34 PA15, 35 PB4, 36 GND, 37 PA14-SWCLK, 38 PA13-SWDIO, 39 PA12, 40 PA11, 41 PB2, 42 PB1, 43 PB0, 44 PB15, 45 GND, 46 BOOT0, 47 GND, 48 NRST, 49 GND, 50 ANTOUT, 51 ANTIN, 52 GND, 53 GND, 54 GND, 55 GND, 56 GNDF2, 57 GND, 58 GND, 59 GNDF2, 60 GND, 61 GND, 62 GND, 63 GND, 64 GND, 65 GND, 66 GND, 67 GND, 68 GND, 69 GND, 70 GND, 71 GND, 72 GND, 73 GND, 74 GND, 75 GND, 76 GND

## STM32WBA52CGU6
designator U?
part A pins: 1 PB12, 2 PB11, 3 PA8, 4 PA7, 5 PA6, 7 PA5, 8 PA3, 9 PB10, 10 PA2, 12 PA1, 13 PA0, 14 PB9, 15 PB8, 16 PC15-OSC32_OUT, 17 PC14-OSC32_IN, 18 PC13, 19 PB7, 20 PB6, 21 PB5, 23 PB4, 24 PB3, 25 PA15, 26 PA14-SWCLK, 27 PA13-SWDIO, 28 PA12, 29 PA11, 30 PB2, 31 PB1, 32 PB0, 33 PB15, 34 PH3-BOOT0, 36 NRST, 40 OSC_OUT, 41 OSC_IN, 45 PA10, 46 PA9, 47 PB14, 48 PB13
part B pins: 6 VDDA, 11 VDD, 22 VDD, 35 VDD, 43 VDD, 44 VCAP, 49 VSS (ExPAD)
part C pins: 37 RF, 38 VDDHPA, 39 VDDRF, 42 VDDRFPA

## STM32WBA54CGU6
designator U?
part A pins: 1 PB12, 2 PB11, 3 PA8, 4 PA7, 5 PA6, 7 PA5, 8 PA3, 9 PB10, 10 PA2, 12 PA1, 13 PA0, 14 PB9, 15 PB8, 16 PC15-OSC32_OUT, 17 PC14-OSC32_IN, 18 PC13, 19 PB7, 20 PB6, 21 PB5, 23 PB4, 24 PB3, 25 PA15, 26 PA14-SWCLK, 27 PA13-SWDIO, 28 PA12, 29 PA11, 30 PB2, 31 PB1, 32 PB0, 33 PB15, 34 PH3-BOOT0, 36 NRST, 40 OSC_OUT, 41 OSC_IN, 45 PA10, 46 PA9, 47 PB14, 48 PB13
part B pins: 6 VDDA, 11 VDD, 22 VDD, 35 VDD, 43 VDD, 44 VCAP, 49 VSS (ExPAD)
part C pins: 37 RF, 38 VDDHPA, 39 VDDRF, 42 VDDRFPA

## STM32WBA54KGU6
designator U?
part A pins: 1 PB12, 2 PA8, 3 PA7, 4 PA6, 6 PA5, 7 PA2, 8 PA1, 9 PA0, 10 PB9, 11 PB8, 12 PC15-OSC32_OUT, 13 PC14-OSC32_IN, 15 PB4, 16 PB3, 17 PA15, 18 PA14-SWCLK, 19 PA13-SWDIO, 20 PA12, 21 PB15, 22 PH3-BOOT0, 24 NRST, 28 OSC_OUT, 29 OSC_IN
part B pins: 5 VDDA, 14 VDD, 23 VDD, 31 VDD, 32 VCAP, 33 VSS (ExPAD)
part C pins: 25 RF, 26 VDDHPA, 27 VDDRF, 30 VDDRFPA

## STM32WBA55CGU6
designator U?
part A pins: 4 PB12, 5 PA8, 6 PA7, 7 PA6, 9 PA5, 10 PA2, 12 PA1, 13 PA0, 14 PB9, 15 PB8, 16 PC15-OSC32_OUT, 17 PC14-OSC32_IN, 18 PC13, 19 PB7, 20 PB6, 21 PB5, 23 PB4, 24 PB3, 25 PA15, 26 PA14-SWCLK, 27 PA13-SWDIO, 28 PA12, 29 PA11, 30 PB2, 31 PB1, 32 PB0, 33 PB15, 34 PH3-BOOT0, 36 NRST, 41 OSC_OUT, 42 OSC_IN, 46 PA10, 47 PA9, 48 PB14
part B pins: 1 VSSSMPS, 2 VDDSMPS, 3 VLXSMPS, 8 VDDA, 11 VDD, 22 VDD, 35 VDD, 39 VDDANA, 44 VDD, 45 VDD11, 49 VSS (ExPAD)
part C pins: 37 RF, 38 VDDHPA, 40 VDDRF, 43 VDDRFPA

## STM32WBA55HG
designator U?
part A pins: A8 OSC_IN, B7 OSC_OUT, C8 PH3-BOOT0, C10 PB12, D7 PA8, D9 PA6, D11 PA7, E2 NRST, E4 PB15, E6 PA12, E8 PA13-SWDIO, E10 PA1, F1 PA14-SWCLK, F3 PA15, F5 PB4, F7 PC15-OSC32_OUT, F9 PB9, F11 PA2, F13 PA5, G2 PB3, G8 PC14-OSC32_IN, G10 PB8, G12 PA0
part B pins: A10 VDD, A12 VSSSMPS, B5 VDDANA, B9 VSS, B11 VDD11, B13 VDDSMPS, C12 VLXSMPS, D13 VSSA, E12 VDDA, G4 VDD, G6 VSS
part C pins: A6 VDDRF, C2 RF, C4 VDDHPA, C6 VDDRFPA, D1 VSSRF, D3 VSSRF, D5 VSSRF

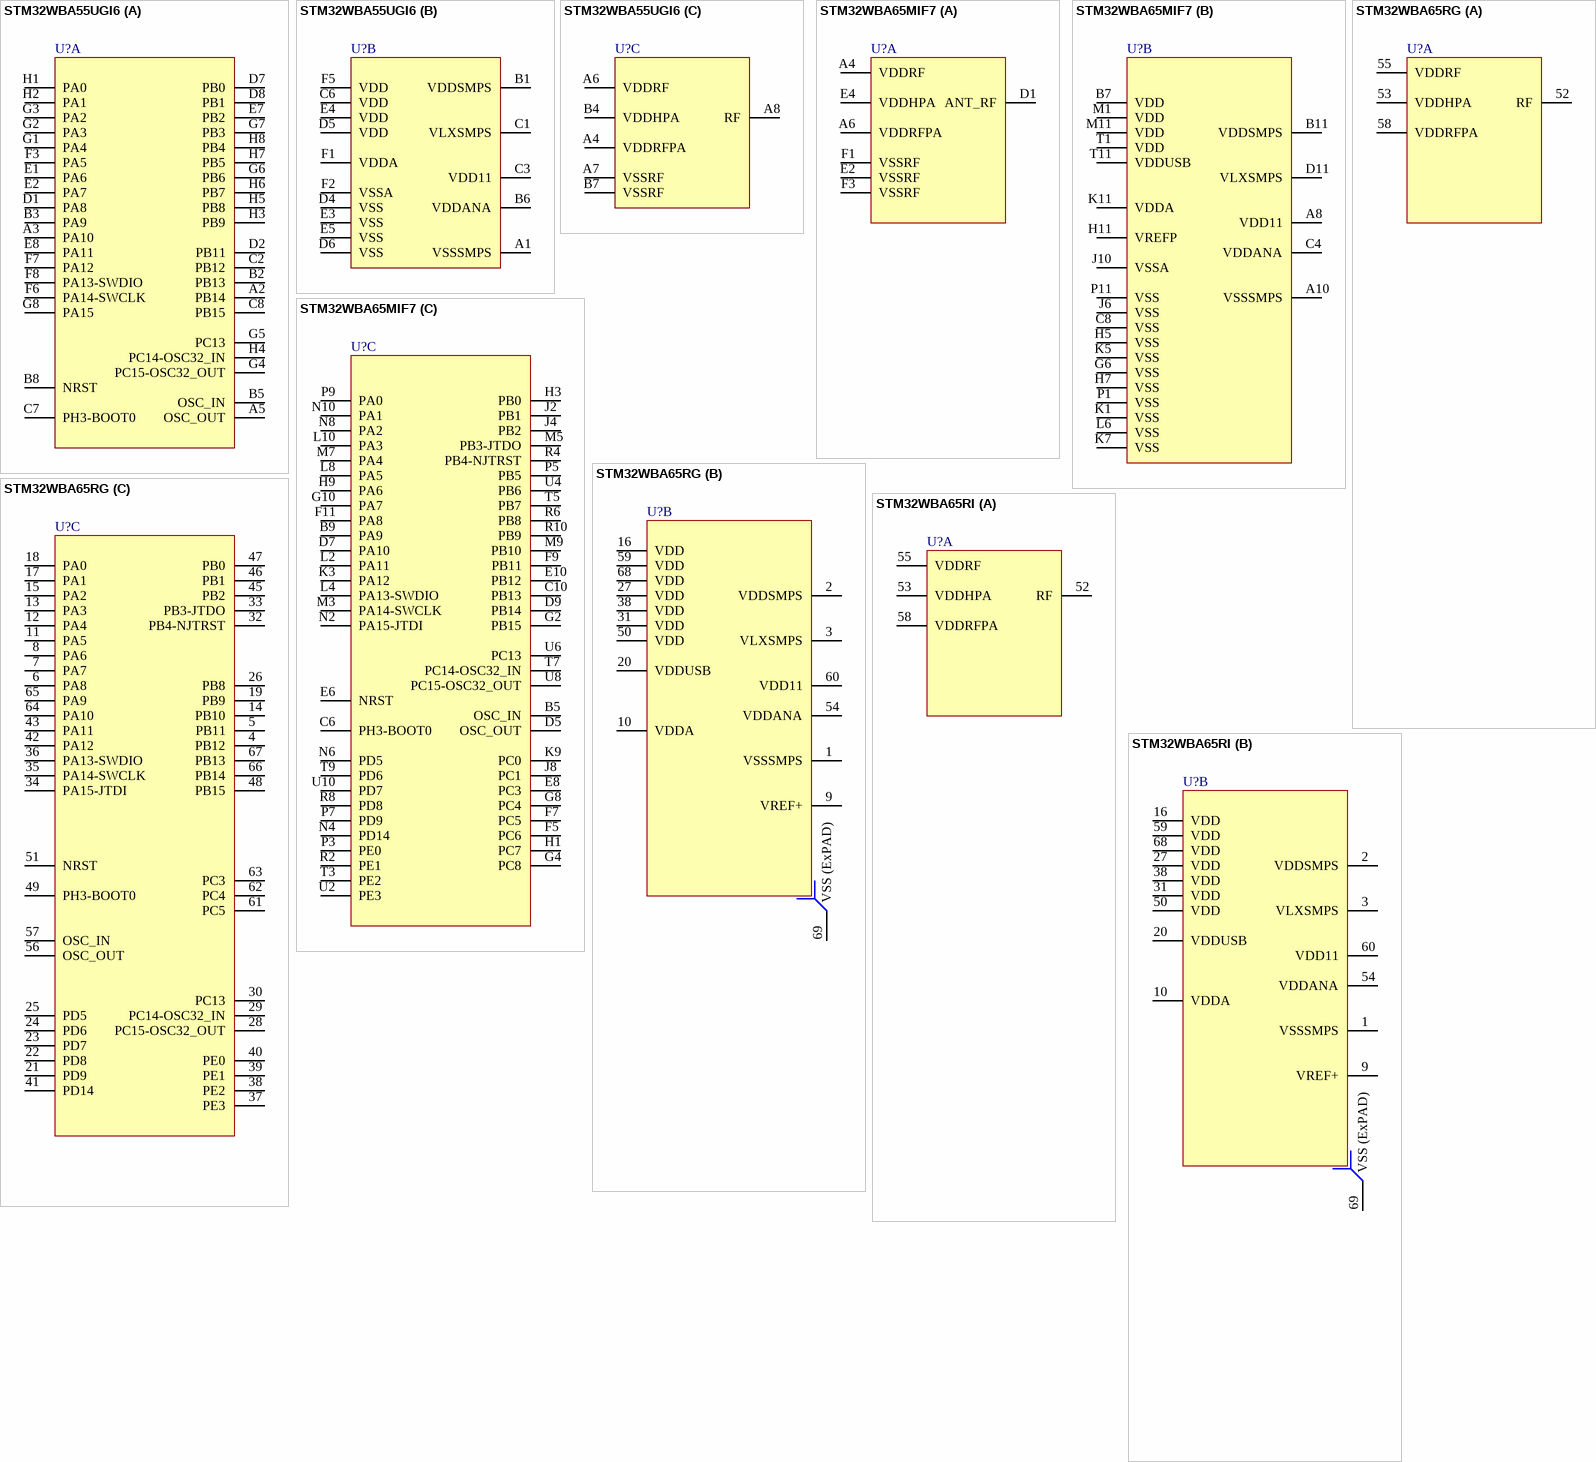
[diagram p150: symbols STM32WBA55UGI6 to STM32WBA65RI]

## STM32WBA55UGI6
designator U?
part A pins: A2 PB14, A3 PA10, A5 OSC_OUT, B2 PB13, B3 PA9, B5 OSC_IN, B8 NRST, C2 PB12, C7 PH3-BOOT0, C8 PB15, D1 PA8, D2 PB11, D7 PB0, D8 PB1, E1 PA6, E2 PA7, E7 PB2, E8 PA11, F3 PA5, F6 PA14-SWCLK, F7 PA12, F8 PA13-SWDIO, G1 PA4, G2 PA3, G3 PA2, G4 PC15-OSC32_OUT, G5 PC13, G6 PB6, G7 PB3, G8 PA15, H1 PA0, H2 PA1, H3 PB9, H4 PC14-OSC32_IN, H5 PB8, H6 PB7, H7 PB5, H8 PB4
part B pins: A1 VSSSMPS, B1 VDDSMPS, B6 VDDANA, C1 VLXSMPS, C3 VDD11, C6 VDD, D4 VSS, D5 VDD, D6 VSS, E3 VSS, E4 VDD, E5 VSS, F1 VDDA, F2 VSSA, F5 VDD
part C pins: A4 VDDRFPA, A6 VDDRF, A7 VSSRF, A8 RF, B4 VDDHPA, B7 VSSRF

## STM32WBA65MIF7
designator U?
part A pins: A4 VDDRF, A6 VDDRFPA, D1 ANT_RF, E2 VSSRF, E4 VDDHPA, F1 VSSRF, F3 VSSRF
part B pins: A8 VDD11, A10 VSSSMPS, B7 VDD, B11 VDDSMPS, C4 VDDANA, C8 VSS, D11 VLXSMPS, G6 VSS, H5 VSS, H7 VSS, H11 VREFP, J6 VSS, J10 VSSA, K1 VSS, K5 VSS, K7 VSS, K11 VDDA, L6 VSS, M1 VDD, M11 VDD, P1 VSS, P11 VSS, T1 VDD, T11 VDDUSB
part C pins: B5 OSC_IN, B9 PA9, C6 PH3-BOOT0, C10 PB13, D5 OSC_OUT, D7 PA10, D9 PB14, E6 NRST, E8 PC3, E10 PB12, F5 PC6, F7 PC5, F9 PB11, F11 PA8, G2 PB15, G4 PC8, G8 PC4, G10 PA7, H1 PC7, H3 PB0, H9 PA6, J2 PB1, J4 PB2, J8 PC1, K3 PA12, K9 PC0, L2 PA11, L4 PA13-SWDIO, L8 PA5, L10 PA3, M3 PA14-SWCLK, M5 PB3-JTDO, M7 PA4, M9 PB10, N2 PA15-JTDI, N4 PD14, N6 PD5, N8 PA2, N10 PA1, P3 PE0, P5 PB5, P7 PD9, P9 PA0, R2 PE1, R4 PB4-NJTRST, R6 PB8, R8 PD8, R10 PB9, T3 PE2, T5 PB7, T7 PC14-OSC32_IN, T9 PD6, U2 PE3, U4 PB6, U6 PC13, U8 PC15-OSC32_OUT, U10 PD7

## STM32WBA65RG
designator U?
part A pins: 52 RF, 53 VDDHPA, 55 VDDRF, 58 VDDRFPA
part B pins: 1 VSSSMPS, 2 VDDSMPS, 3 VLXSMPS, 9 VREF+, 10 VDDA, 16 VDD, 20 VDDUSB, 27 VDD, 31 VDD, 38 VDD, 50 VDD, 54 VDDANA, 59 VDD, 60 VDD11, 68 VDD, 69 VSS (ExPAD)
part C pins: 4 PB12, 5 PB11, 6 PA8, 7 PA7, 8 PA6, 11 PA5, 12 PA4, 13 PA3, 14 PB10, 15 PA2, 17 PA1, 18 PA0, 19 PB9, 21 PD9, 22 PD8, 23 PD7, 24 PD6, 25 PD5, 26 PB8, 28 PC15-OSC32_OUT, 29 PC14-OSC32_IN, 30 PC13, 32 PB4-NJTRST, 33 PB3-JTDO, 34 PA15-JTDI, 35 PA14-SWCLK, 36 PA13-SWDIO, 37 PE3, 38 PE2, 39 PE1, 40 PE0, 41 PD14, 42 PA12, 43 PA11, 45 PB2, 46 PB1, 47 PB0, 48 PB15, 49 PH3-BOOT0, 51 NRST, 56 OSC_OUT, 57 OSC_IN, 61 PC5, 62 PC4, 63 PC3, 64 PA10, 65 PA9, 66 PB14, 67 PB13

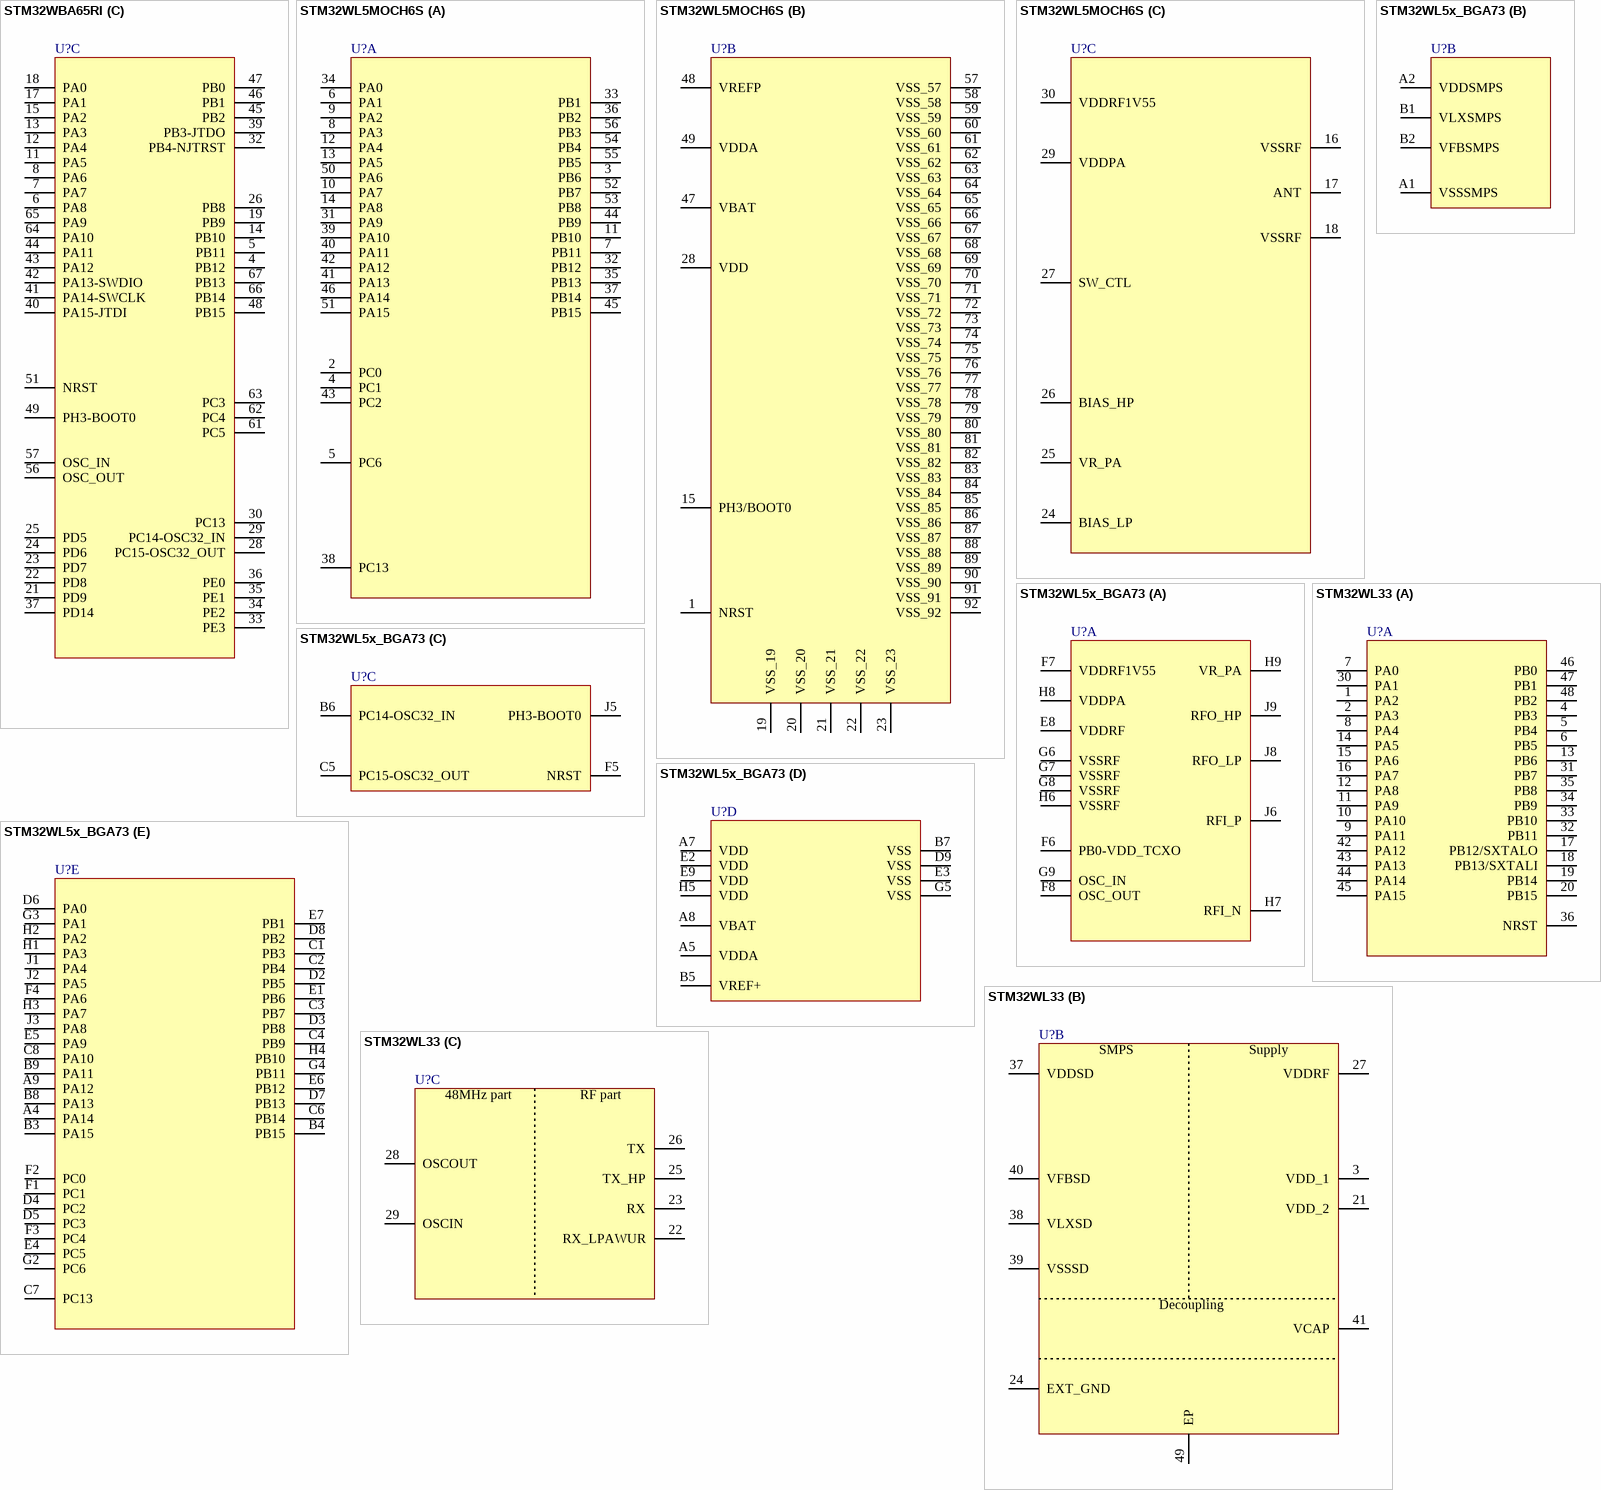
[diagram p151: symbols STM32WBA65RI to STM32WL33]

## STM32WBA65RI
designator U?
part A pins: 52 RF, 53 VDDHPA, 55 VDDRF, 58 VDDRFPA
part B pins: 1 VSSSMPS, 2 VDDSMPS, 3 VLXSMPS, 9 VREF+, 10 VDDA, 16 VDD, 20 VDDUSB, 27 VDD, 31 VDD, 38 VDD, 50 VDD, 54 VDDANA, 59 VDD, 60 VDD11, 68 VDD, 69 VSS (ExPAD)
part C pins: 4 PB12, 5 PB11, 6 PA8, 7 PA7, 8 PA6, 11 PA5, 12 PA4, 13 PA3, 14 PB10, 15 PA2, 17 PA1, 18 PA0, 19 PB9, 21 PD9, 22 PD8, 23 PD7, 24 PD6, 25 PD5, 26 PB8, 28 PC15-OSC32_OUT, 29 PC14-OSC32_IN, 30 PC13, 32 PB4-NJTRST, 33 PE3, 34 PE2, 35 PE1, 36 PE0, 37 PD14, 39 PB3-JTDO, 40 PA15-JTDI, 41 PA14-SWCLK, 42 PA13-SWDIO, 43 PA12, 44 PA11, 45 PB2, 46 PB1, 47 PB0, 48 PB15, 49 PH3-BOOT0, 51 NRST, 56 OSC_OUT, 57 OSC_IN, 61 PC5, 62 PC4, 63 PC3, 64 PA10, 65 PA9, 66 PB14, 67 PB13

## STM32WL5MOCH6S
designator U?
part A pins: 2 PC0, 3 PB6, 4 PC1, 5 PC6, 6 PA1, 7 PB11, 8 PA3, 9 PA2, 10 PA7, 11 PB10, 12 PA4, 13 PA5, 14 PA8, 31 PA9, 32 PB12, 33 PB1, 34 PA0, 35 PB13, 36 PB2, 37 PB14, 38 PC13, 39 PA10, 40 PA11, 41 PA13, 42 PA12, 43 PC2, 44 PB9, 45 PB15, 46 PA14, 50 PA6, 51 PA15, 52 PB7, 53 PB8, 54 PB4, 55 PB5, 56 PB3
part B pins: 1 NRST, 15 PH3/BOOT0, 19 VSS_19, 20 VSS_20, 21 VSS_21, 22 VSS_22, 23 VSS_23, 28 VDD, 47 VBAT, 48 VREFP, 49 VDDA, 57 VSS_57, 58 VSS_58, 59 VSS_59, 60 VSS_60, 61 VSS_61, 62 VSS_62, 63 VSS_63, 64 VSS_64, 65 VSS_65, 66 VSS_66, 67 VSS_67, 68 VSS_68, 69 VSS_69, 70 VSS_70, 71 VSS_71, 72 VSS_72, 73 VSS_73, 74 VSS_74, 75 VSS_75, 76 VSS_76, 77 VSS_77, 78 VSS_78, 79 VSS_79, 80 VSS_80, 81 VSS_81, 82 VSS_82, 83 VSS_83, 84 VSS_84, 85 VSS_85, 86 VSS_86, 87 VSS_87, 88 VSS_88, 89 VSS_89, 90 VSS_90, 91 VSS_91, 92 VSS_92
part C pins: 16 VSSRF, 17 ANT, 18 VSSRF, 24 BIAS_LP, 25 VR_PA, 26 BIAS_HP, 27 SW_CTL, 29 VDDPA, 30 VDDRF1V55

## STM32WL5x_BGA73
designator U?
part A pins: E8 VDDRF, F6 PB0-VDD_TCXO, F7 VDDRF1V55, F8 OSC_OUT, G6 VSSRF, G7 VSSRF, G8 VSSRF, G9 OSC_IN, H6 VSSRF, H7 RFI_N, H8 VDDPA, H9 VR_PA, J6 RFI_P, J8 RFO_LP, J9 RFO_HP
part B pins: A1 VSSSMPS, A2 VDDSMPS, B1 VLXSMPS, B2 VFBSMPS
part C pins: B6 PC14-OSC32_IN, C5 PC15-OSC32_OUT, F5 NRST, J5 PH3-BOOT0
part D pins: A5 VDDA, A7 VDD, A8 VBAT, B5 VREF+, B7 VSS, D9 VSS, E2 VDD, E3 VSS, E9 VDD, G5 VSS, H5 VDD
part E pins: A4 PA14, A9 PA12, B3 PA15, B4 PB15, B8 PA13, B9 PA11, C1 PB3, C2 PB4, C3 PB7, C4 PB9, C6 PB14, C7 PC13, C8 PA10, D2 PB5, D3 PB8, D4 PC2, D5 PC3, D6 PA0, D7 PB13, D8 PB2, E1 PB6, E4 PC5, E5 PA9, E6 PB12, E7 PB1, F1 PC1, F2 PC0, F3 PC4, F4 PA6, G2 PC6, G3 PA1, G4 PB11, H1 PA3, H2 PA2, H3 PA7, H4 PB10, J1 PA4, J2 PA5, J3 PA8

## STM32WL33
designator U?
part A pins: 1 PA2, 2 PA3, 4 PB3, 5 PB4, 6 PB5, 7 PA0, 8 PA4, 9 PA11, 10 PA10, 11 PA9, 12 PA8, 13 PB6, 14 PA5, 15 PA6, 16 PA7, 17 PB12/SXTALO, 18 PB13/SXTALI, 19 PB14, 20 PB15, 30 PA1, 31 PB7, 32 PB11, 33 PB10, 34 PB9, 35 PB8, 36 NRST, 42 PA12, 43 PA13, 44 PA14, 45 PA15, 46 PB0, 47 PB1, 48 PB2
part B pins: 3 VDD_1, 21 VDD_2, 24 EXT_GND, 27 VDDRF, 37 VDDSD, 38 VLXSD, 39 VSSSD, 40 VFBSD, 41 VCAP, 49 EP
part C pins: 22 RX_LPAWUR, 23 RX, 25 TX_HP, 26 TX, 28 OSCOUT, 29 OSCIN

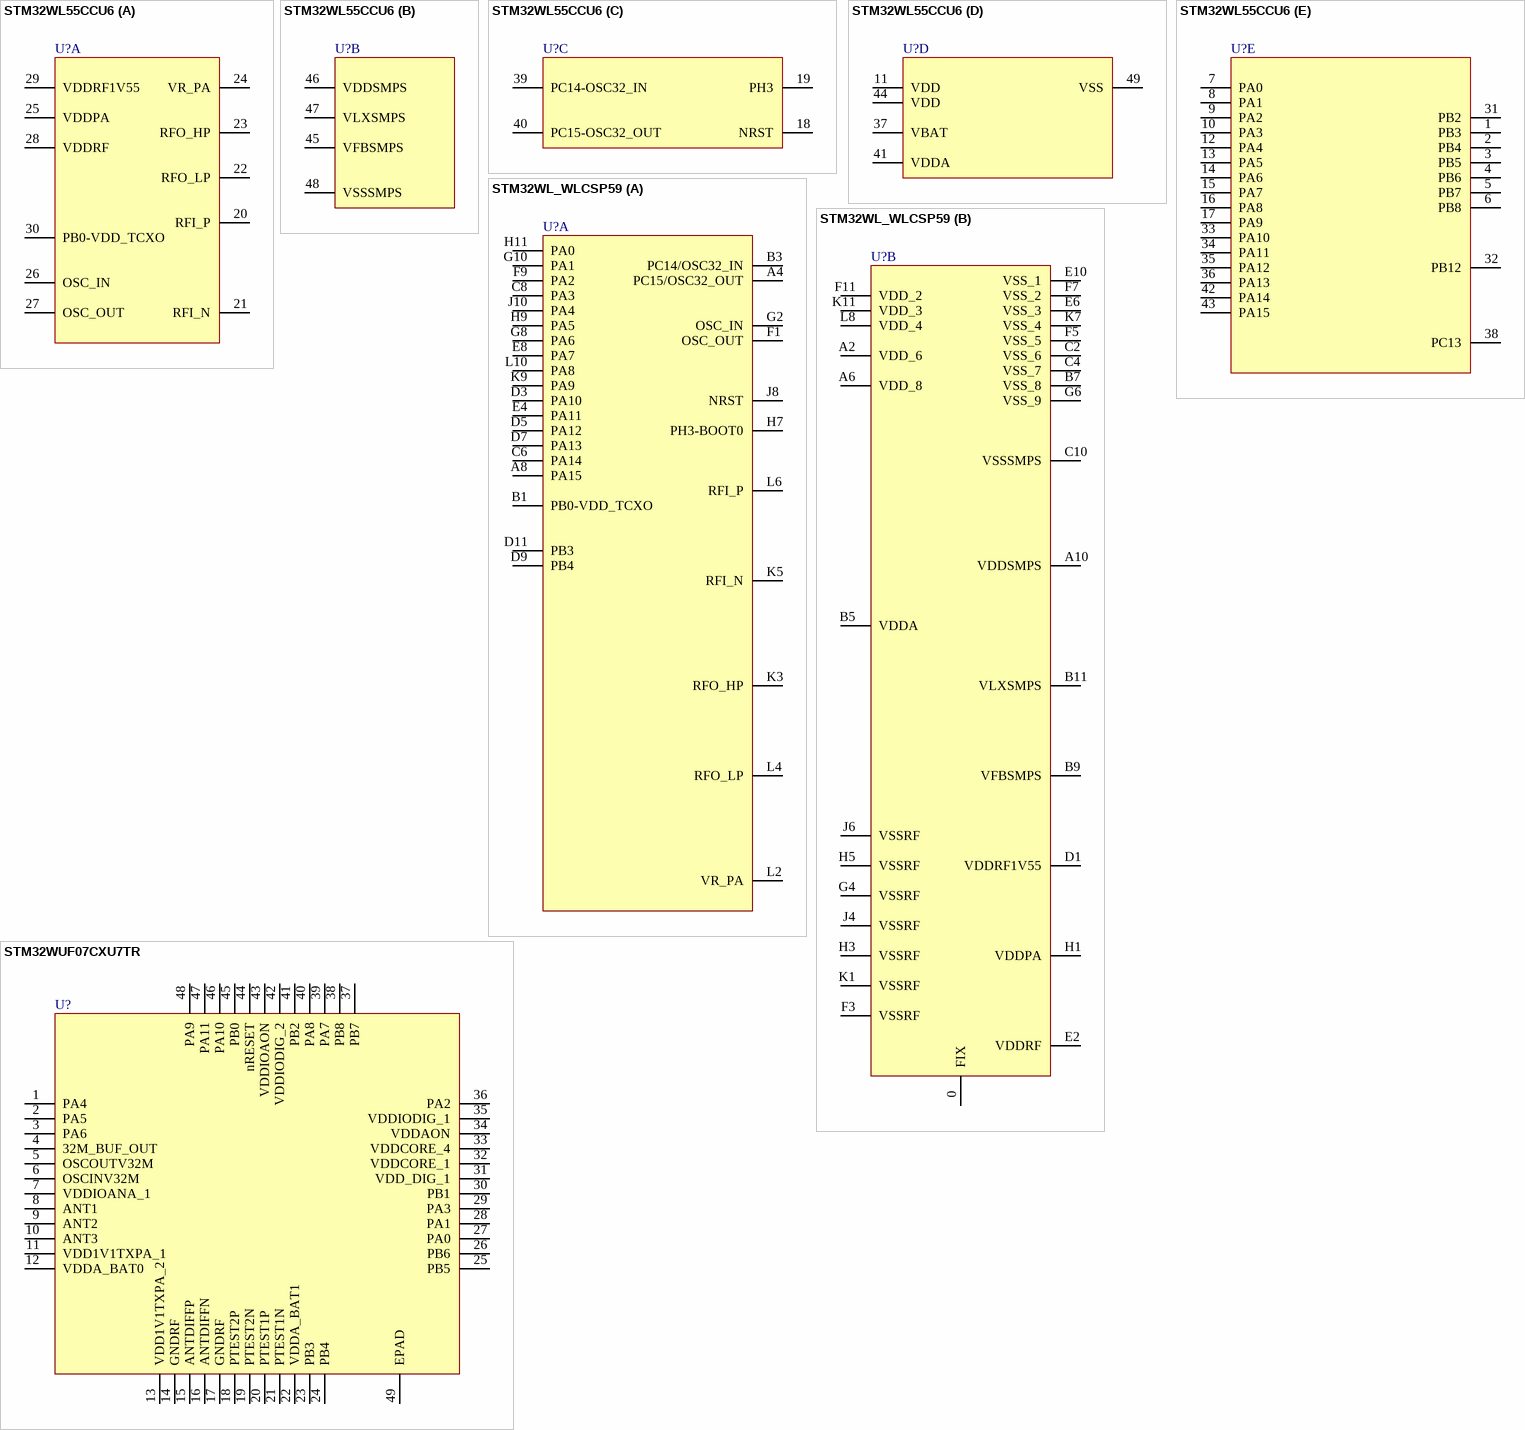
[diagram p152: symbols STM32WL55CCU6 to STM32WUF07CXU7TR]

## STM32WL55CCU6
designator U?
part A pins: 20 RFI_P, 21 RFI_N, 22 RFO_LP, 23 RFO_HP, 24 VR_PA, 25 VDDPA, 26 OSC_IN, 27 OSC_OUT, 28 VDDRF, 29 VDDRF1V55, 30 PB0-VDD_TCXO
part B pins: 45 VFBSMPS, 46 VDDSMPS, 47 VLXSMPS, 48 VSSSMPS
part C pins: 18 NRST, 19 PH3, 39 PC14-OSC32_IN, 40 PC15-OSC32_OUT
part D pins: 11 VDD, 37 VBAT, 41 VDDA, 44 VDD, 49 VSS
part E pins: 1 PB3, 2 PB4, 3 PB5, 4 PB6, 5 PB7, 6 PB8, 7 PA0, 8 PA1, 9 PA2, 10 PA3, 12 PA4, 13 PA5, 14 PA6, 15 PA7, 16 PA8, 17 PA9, 31 PB2, 32 PB12, 33 PA10, 34 PA11, 35 PA12, 36 PA13, 38 PC13, 42 PA14, 43 PA15

## STM32WL_WLCSP59
designator U?
part A pins: A4 PC15/OSC32_OUT, A8 PA15, B1 PB0-VDD_TCXO, B3 PC14/OSC32_IN, C6 PA14, C8 PA3, D3 PA10, D5 PA12, D7 PA13, D9 PB4, D11 PB3, E4 PA11, E8 PA7, F1 OSC_OUT, F9 PA2, G2 OSC_IN, G8 PA6, G10 PA1, H7 PH3-BOOT0, H9 PA5, H11 PA0, J8 NRST, J10 PA4, K3 RFO_HP, K5 RFI_N, K9 PA9, L2 VR_PA, L4 RFO_LP, L6 RFI_P, L10 PA8
part B pins: 0 FIX, A2 VDD_6, A6 VDD_8, A10 VDDSMPS, B5 VDDA, B7 VSS_8, B9 VFBSMPS, B11 VLXSMPS, C2 VSS_6, C4 VSS_7, C10 VSSSMPS, D1 VDDRF1V55, E2 VDDRF, E6 VSS_3, E10 VSS_1, F3 VSSRF, F5 VSS_5, F7 VSS_2, F11 VDD_2, G4 VSSRF, G6 VSS_9, H1 VDDPA, H3 VSSRF, H5 VSSRF, J4 VSSRF, J6 VSSRF, K1 VSSRF, K7 VSS_4, K11 VDD_3, L8 VDD_4

## STM32WUF07CXU7TR
designator U?
pins: 1 PA4, 2 PA5, 3 PA6, 4 32M_BUF_OUT, 5 OSCOUTV32M, 6 OSCINV32M, 7 VDDIOANA_1, 8 ANT1, 9 ANT2, 10 ANT3, 11 VDD1V1TXPA_1, 12 VDDA_BAT0, 13 VDD1V1TXPA_2, 14 GNDRF, 15 ANTDIFFP, 16 ANTDIFFN, 17 GNDRF, 18 PTEST2P, 19 PTEST2N, 20 PTEST1P, 21 PTEST1N, 22 VDDA_BAT1, 23 PB3, 24 PB4, 25 PB5, 26 PB6, 27 PA0, 28 PA1, 29 PA3, 30 PB1, 31 VDD_DIG_1, 32 VDDCORE_1, 33 VDDCORE_4, 34 VDDAON, 35 VDDIODIG_1, 36 PA2, 37 PB7, 38 PB8, 39 PA7, 40 PA8, 41 PB2, 42 VDDIODIG_2, 43 VDDIOAON, 44 nRESET, 45 PB0, 46 PA10, 47 PA11, 48 PA9, 49 EPAD

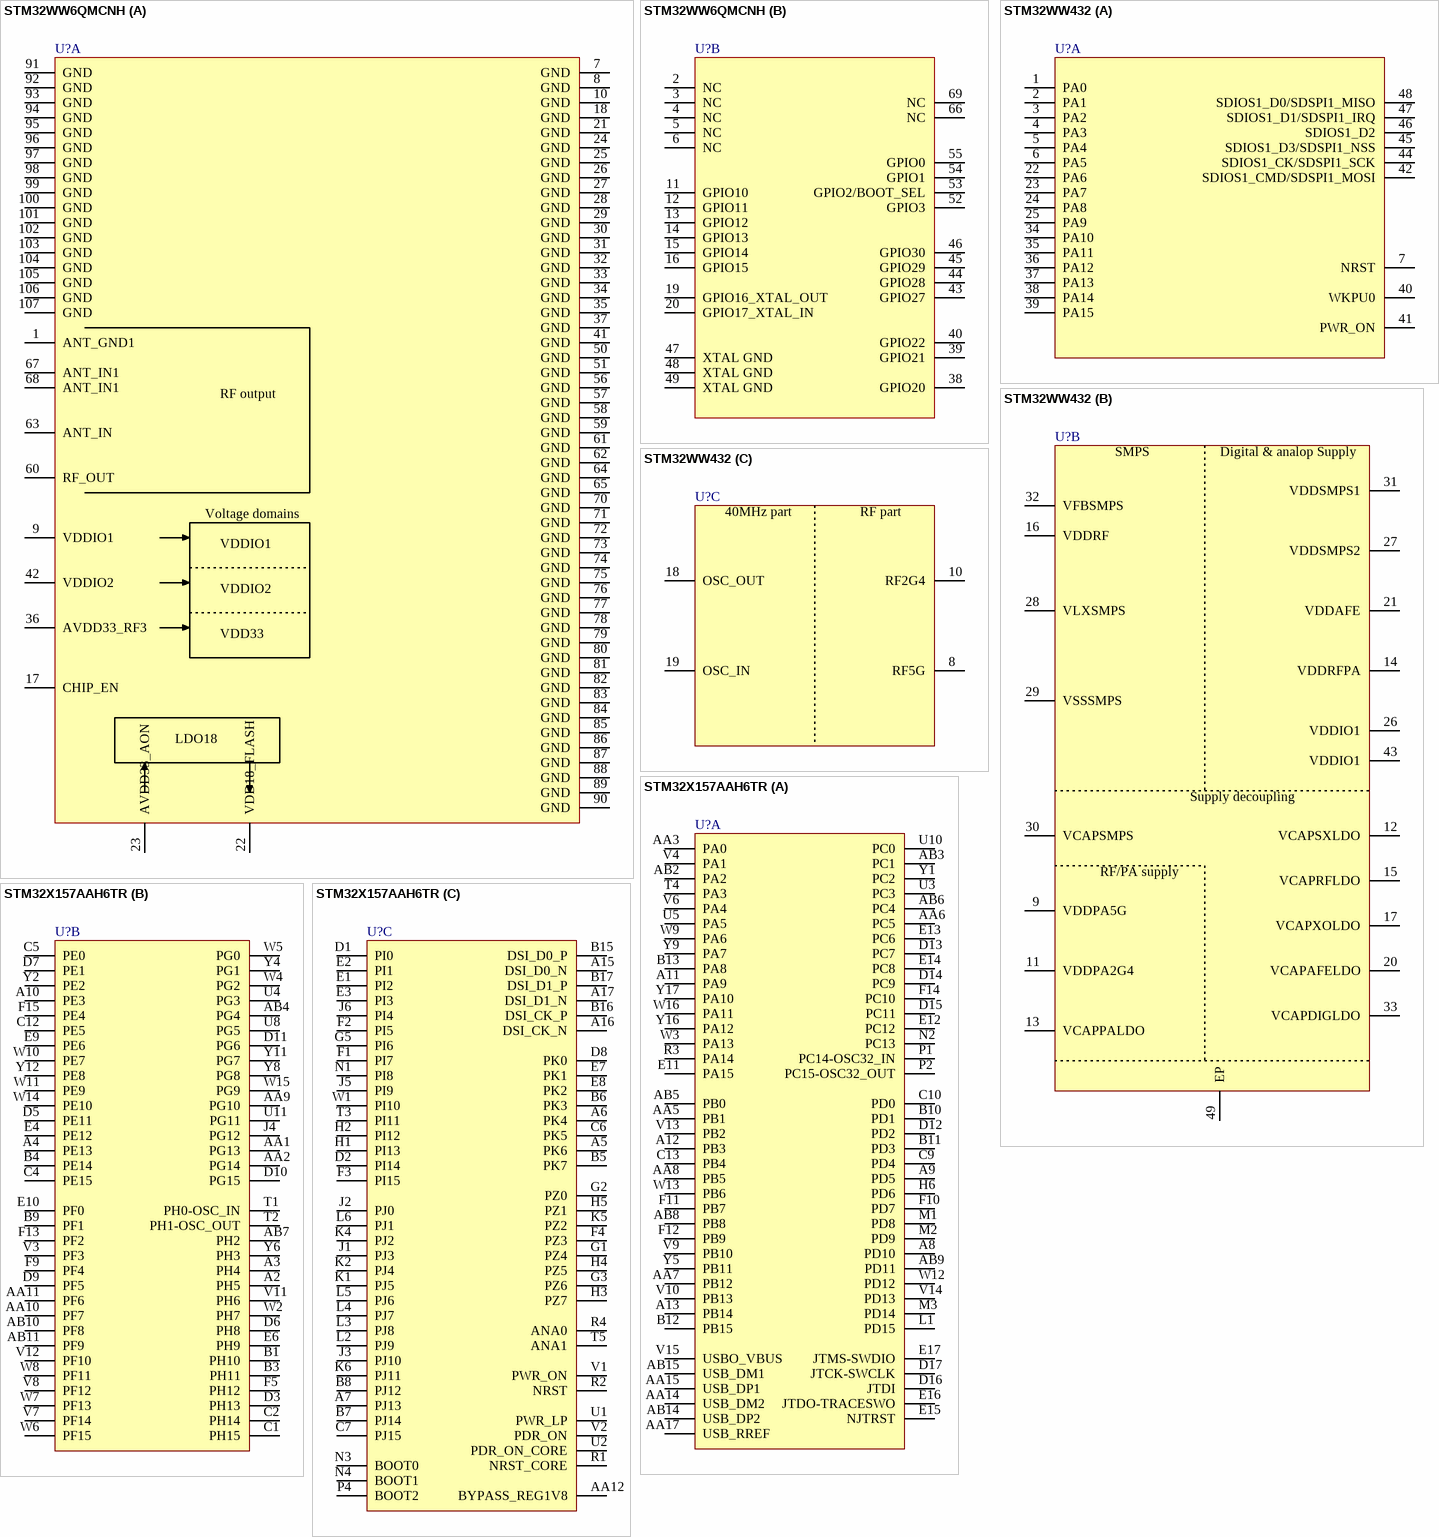
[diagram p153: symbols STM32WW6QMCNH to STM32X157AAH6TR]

## STM32WW6QMCNH
designator U?
part A pins: 1 ANT_GND1, 7 GND, 8 GND, 9 VDDIO1, 10 GND, 17 CHIP_EN, 18 GND, 21 GND, 22 VDD18_FLASH, 23 AVDD33_AON, 24 GND, 25 GND, 26 GND, 27 GND, 28 GND, 29 GND, 30 GND, 31 GND, 32 GND, 33 GND, 34 GND, 35 GND, 36 AVDD33_RF3, 37 GND, 41 GND, 42 VDDIO2, 50 GND, 51 GND, 56 GND, 57 GND, 58 GND, 59 GND, 60 RF_OUT, 61 GND, 62 GND, 63 ANT_IN, 64 GND, 65 GND, 67 ANT_IN1, 68 ANT_IN1, 70 GND, 71 GND, 72 GND, 73 GND, 74 GND, 75 GND, 76 GND, 77 GND, 78 GND, 79 GND, 80 GND, 81 GND, 82 GND, 83 GND, 84 GND, 85 GND, 86 GND, 87 GND, 88 GND, 89 GND, 90 GND, 91 GND, 92 GND, 93 GND, 94 GND, 95 GND, 96 GND, 97 GND, 98 GND, 99 GND, 100 GND, 101 GND, 102 GND, 103 GND, 104 GND, 105 GND, 106 GND, 107 GND
part B pins: 2 NC, 3 NC, 4 NC, 5 NC, 6 NC, 11 GPIO10, 12 GPIO11, 13 GPIO12, 14 GPIO13, 15 GPIO14, 16 GPIO15, 19 GPIO16_XTAL_OUT, 20 GPIO17_XTAL_IN, 38 GPIO20, 39 GPIO21, 40 GPIO22, 43 GPIO27, 44 GPIO28, 45 GPIO29, 46 GPIO30, 47 XTAL GND, 48 XTAL GND, 49 XTAL GND, 52 GPIO3, 53 GPIO2/BOOT_SEL, 54 GPIO1, 55 GPIO0, 66 NC, 69 NC

## STM32WW432
designator U?
part A pins: 1 PA0, 2 PA1, 3 PA2, 4 PA3, 5 PA4, 6 PA5, 7 NRST, 22 PA6, 23 PA7, 24 PA8, 25 PA9, 34 PA10, 35 PA11, 36 PA12, 37 PA13, 38 PA14, 39 PA15, 40 WKPU0, 41 PWR_ON, 42 SDIOS1_CMD/SDSPI1_MOSI, 44 SDIOS1_CK/SDSPI1_SCK, 45 SDIOS1_D3/SDSPI1_NSS, 46 SDIOS1_D2, 47 SDIOS1_D1/SDSPI1_IRQ, 48 SDIOS1_D0/SDSPI1_MISO
part B pins: 9 VDDPA5G, 11 VDDPA2G4, 12 VCAPSXLDO, 13 VCAPPALDO, 14 VDDRFPA, 15 VCAPRFLDO, 16 VDDRF, 17 VCAPXOLDO, 20 VCAPAFELDO, 21 VDDAFE, 26 VDDIO1, 27 VDDSMPS2, 28 VLXSMPS, 29 VSSSMPS, 30 VCAPSMPS, 31 VDDSMPS1, 32 VFBSMPS, 33 VCAPDIGLDO, 43 VDDIO1, 49 EP
part C pins: 8 RF5G, 10 RF2G4, 18 OSC_OUT, 19 OSC_IN

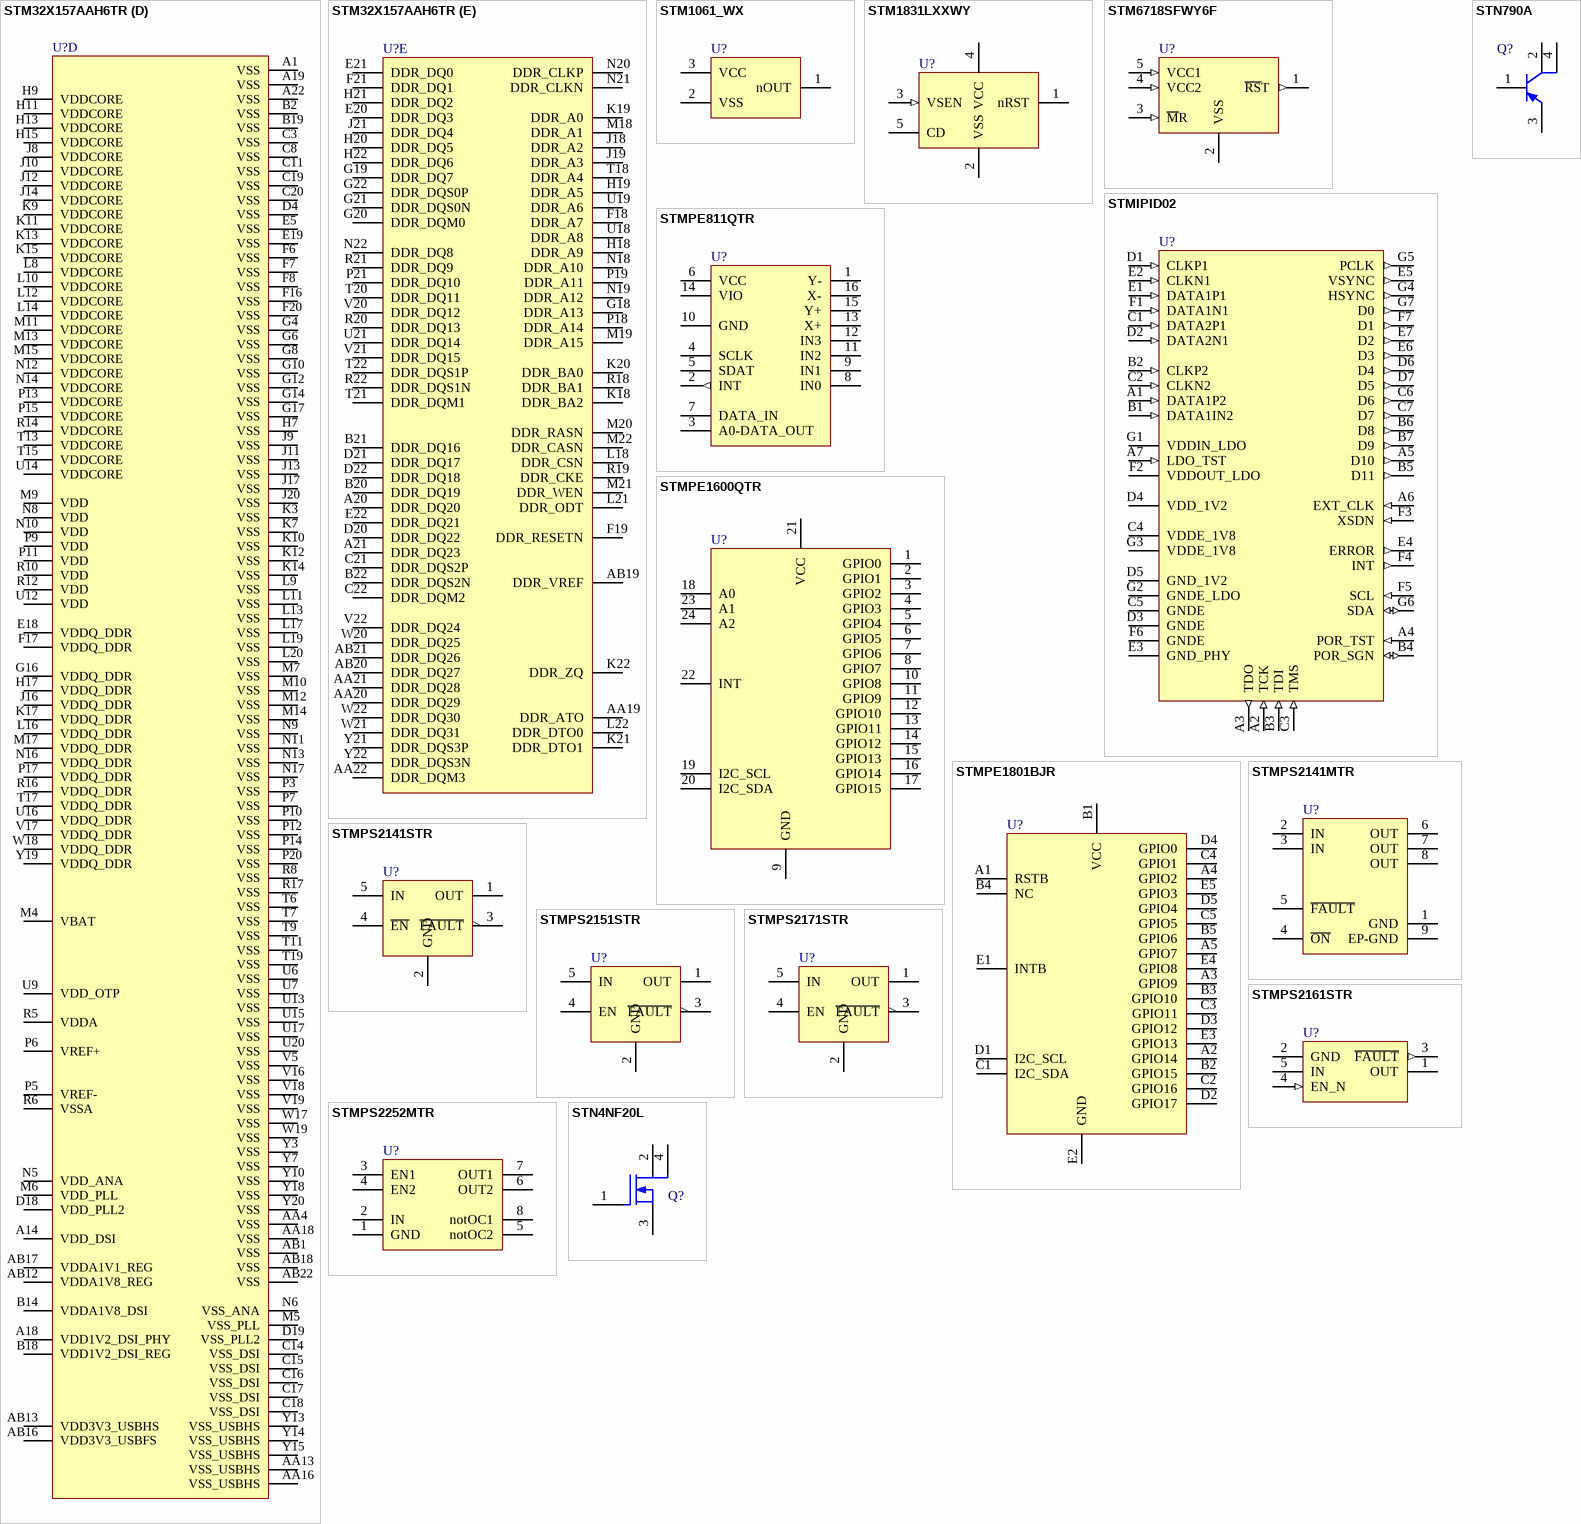
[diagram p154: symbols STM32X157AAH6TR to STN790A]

## STM32X157AAH6TR
designator U?
part A pins: A8 PD10, A9 PD5, A11 PA9, A12 PB3, A13 PB14, AA3 PA0, AA5 PB1, AA6 PC5, AA7 PB12, AA8 PB5, AA14 USB_DM2, AA15 USB_DP1, AA17 USB_RREF, AB2 PA2, AB3 PC1, AB5 PB0, AB6 PC4, AB8 PB8, AB9 PD11, AB14 USB_DP2, AB15 USB_DM1, B10 PD1, B11 PD3, B12 PB15, B13 PA8, C9 PD4, C10 PD0, C13 PB4, D12 PD2, D13 PC7, D14 PC9, D15 PC11, D16 JTDI, D17 JTCK-SWCLK, E11 PA15, E12 PC12, E13 PC6, E14 PC8, E15 NJTRST, E16 JTDO-TRACESWO, E17 JTMS-SWDIO, F10 PD7, F11 PB7, F12 PB9, F14 PC10, H6 PD6, L1 PD15, M1 PD8, M2 PD9, M3 PD14, N2 PC13, P1 PC14-OSC32_IN, P2 PC15-OSC32_OUT, R3 PA14, T4 PA3, U3 PC3, U5 PA5, U10 PC0, V4 PA1, V6 PA4, V9 PB10, V10 PB13, V13 PB2, V14 PD13, V15 USBO_VBUS, W3 PA13, W9 PA6, W12 PD12, W13 PB6, W16 PA11, Y1 PC2, Y5 PB11, Y9 PA7, Y16 PA12, Y17 PA10
part B pins: A2 PH5, A3 PH4, A4 PE13, A10 PE3, AA1 PG13, AA2 PG14, AA9 PG10, AA10 PF7, AA11 PF6, AB4 PG4, AB7 PH2, AB10 PF8, AB11 PF9, B1 PH10, B3 PH11, B4 PE14, B9 PF1, C1 PH15, C2 PH14, C4 PE15, C5 PE0, C12 PE5, D3 PH13, D5 PE11, D6 PH8, D7 PE1, D9 PF5, D10 PG15, D11 PG6, E4 PE12, E6 PH9, E9 PE6, E10 PF0, F5 PH12, F9 PF4, F13 PF2, F15 PE4, J4 PG12, T1 PH0-OSC_IN, T2 PH1-OSC_OUT, U4 PG3, U8 PG5, U11 PG11, V3 PF3, V7 PF14, V8 PF12, V11 PH6, V12 PF10, W2 PH7, W4 PG2, W5 PG0, W6 PF15, W7 PF13, W8 PF11, W10 PE7, W11 PE9, W14 PE10, W15 PG9, Y2 PE2, Y4 PG1, Y6 PH3, Y8 PG8, Y11 PG7, Y12 PE8
part C pins: A5 PK6, A6 PK4, A7 PJ13, A15 DSI_D0_N, A16 DSI_CK_N, A17 DSI_D1_N, AA12 BYPASS_REG1V8, B5 PK7, B6 PK3, B7 PJ14, B8 PJ12, B15 DSI_D0_P, B16 DSI_CK_P, B17 DSI_D1_P, C6 PK5, C7 PJ15, D1 PI0, D2 PI14, D8 PK0, E1 PI2, E2 PI1, E3 PI3, E7 PK1, E8 PK2, F1 PI7, F2 PI5, F3 PI15, F4 PZ3, G1 PZ4, G2 PZ0, G3 PZ6, G5 PI6, H1 PI13, H2 PI12, H3 PZ7, H4 PZ5, H5 PZ1, J1 PJ3, J2 PJ0, J3 PJ10, J5 PI9, J6 PI4, K1 PJ5, K2 PJ4, K4 PJ2, K5 PZ2, K6 PJ11, L2 PJ9, L3 PJ8, L4 PJ7, L5 PJ6, L6 PJ1, N1 PI8, N3 BOOT0, N4 BOOT1, P4 BOOT2, R1 NRST_CORE, R2 NRST, R4 ANA0, T3 PI11, T5 ANA1, U1 PWR_LP, U2 PDR_ON_CORE, V1 PWR_ON, V2 PDR_ON, W1 PI10
part D pins: A1 VSS, A14 VDD_DSI, A18 VDD1V2_DSI_PHY, A19 VSS, A22 VSS, AA4 VSS, AA13 VSS_USBHS, AA16 VSS_USBHS, AA18 VSS, AB1 VSS, AB12 VDDA1V8_REG, AB13 VDD3V3_USBHS, AB16 VDD3V3_USBFS, AB17 VDDA1V1_REG, AB18 VSS, AB22 VSS, B2 VSS, B14 VDDA1V8_DSI, B18 VDD1V2_DSI_REG, B19 VSS, C3 VSS, C8 VSS, C11 VSS, C14 VSS_DSI, C15 VSS_DSI, C16 VSS_DSI, C17 VSS_DSI, C18 VSS_DSI, C19 VSS, C20 VSS, D4 VSS, D18 VDD_PLL2, D19 VSS_PLL2, E5 VSS, E18 VDDQ_DDR, E19 VSS, F6 VSS, F7 VSS, F8 VSS, F16 VSS, F17 VDDQ_DDR, F20 VSS, G4 VSS, G6 VSS, G8 VSS, G10 VSS, G12 VSS, G14 VSS, G16 VDDQ_DDR, G17 VSS, H7 VSS, H9 VDDCORE, H11 VDDCORE, H13 VDDCORE, H15 VDDCORE, H17 VDDQ_DDR, J8 VDDCORE, J9 VSS, J10 VDDCORE, J11 VSS, J12 VDDCORE, J13 VSS, J14 VDDCORE, J16 VDDQ_DDR, J17 VSS, J20 VSS, K3 VSS, K7 VSS, K9 VDDCORE, K10 VSS, K11 VDDCORE, K12 VSS, K13 VDDCORE, K14 VSS, K15 VDDCORE, K17 VDDQ_DDR, L8 VDDCORE, L9 VSS, L10 VDDCORE, L11 VSS, L12 VDDCORE, L13 VSS, L14 VDDCORE, L16 VDDQ_DDR, L17 VSS, L19 VSS, L20 VSS, M4 VBAT, M5 VSS_PLL, M6 VDD_PLL, M7 VSS, M9 VDD, M10 VSS, M11 VDDCORE, M12 VSS, M13 VDDCORE, M14 VSS, M15 VDDCORE, M17 VDDQ_DDR, N5 VDD_ANA, N6 VSS_ANA, N8 VDD, N9 VSS, N10 VDD, N11 VSS, N12 VDDCORE, N13 VSS, N14 VDDCORE, N16 VDDQ_DDR, N17 VSS, P3 VSS, P5 VREF-, P6 VREF+, P7 VSS, P9 VDD, P10 VSS, P11 VDD, P12 VSS, P13 VDDCORE, P14 VSS, P15 VDDCORE, P17 VDDQ_DDR, P20 VSS, R5 VDDA, R6 VSSA, R8 VSS, R10 VDD, R12 VDD, R14 VDDCORE, R16 VDDQ_DDR, R17 VSS, T6 VSS, T7 VSS, T9 VSS, T11 VSS, T13 VDDCORE, T15 VDDCORE, T17 VDDQ_DDR, T19 VSS, U6 VSS, U7 VSS, U9 VDD_OTP, U12 VDD, U13 VSS, U14 VDDCORE, U15 VSS, U16 VDDQ_DDR, U17 VSS, U20 VSS, V5 VSS, V16 VSS, V17 VDDQ_DDR, V18 VSS, V19 VSS, W17 VSS, W18 VDDQ_DDR, W19 VSS, Y3 VSS, Y7 VSS, Y10 VSS, Y13 VSS_USBHS, Y14 VSS_USBHS, Y15 VSS_USBHS, Y18 VSS, Y19 VDDQ_DDR, Y20 VSS
part E pins: A20 DDR_DQ20, A21 DDR_DQ23, AA19 DDR_ATO, AA20 DDR_DQ29, AA21 DDR_DQ28, AA22 DDR_DQM3, AB19 DDR_VREF, AB20 DDR_DQ27, AB21 DDR_DQ26, B20 DDR_DQ19, B21 DDR_DQ16, B22 DDR_DQS2N, C21 DDR_DQS2P, C22 DDR_DQM2, D20 DDR_DQ22, D21 DDR_DQ17, D22 DDR_DQ18, E20 DDR_DQ3, E21 DDR_DQ0, E22 DDR_DQ21, F18 DDR_A7, F19 DDR_RESETN, F21 DDR_DQ1, G18 DDR_A13, G19 DDR_DQ7, G20 DDR_DQM0, G21 DDR_DQS0N, G22 DDR_DQS0P, H18 DDR_A9, H19 DDR_A5, H20 DDR_DQ5, H21 DDR_DQ2, H22 DDR_DQ6, J18 DDR_A2, J19 DDR_A3, J21 DDR_DQ4, K18 DDR_BA2, K19 DDR_A0, K20 DDR_BA0, K21 DDR_DTO1, K22 DDR_ZQ, L18 DDR_CSN, L21 DDR_ODT, L22 DDR_DTO0, M18 DDR_A1, M19 DDR_A15, M20 DDR_RASN, M21 DDR_WEN, M22 DDR_CASN, N18 DDR_A10, N19 DDR_A12, N20 DDR_CLKP, N21 DDR_CLKN, N22 DDR_DQ8, P18 DDR_A14, P19 DDR_A11, P21 DDR_DQ10, R18 DDR_BA1, R19 DDR_CKE, R20 DDR_DQ13, R21 DDR_DQ9, R22 DDR_DQS1N, T18 DDR_A4, T20 DDR_DQ11, T21 DDR_DQM1, T22 DDR_DQS1P, U18 DDR_A8, U19 DDR_A6, U21 DDR_DQ14, V20 DDR_DQ12, V21 DDR_DQ15, V22 DDR_DQ24, W20 DDR_DQ25, W21 DDR_DQ31, W22 DDR_DQ30, Y21 DDR_DQS3P, Y22 DDR_DQS3N

## STM1061_WX
designator U?
pins: 1 nOUT, 2 VSS, 3 VCC

## STM1831LXXWY
designator U?
pins: 1 nRST (oc), 2 VSS, 3 VSEN (in), 4 VCC (power), 5 CD

## STM6718SFWY6F
designator U?
pins: 1 ~{RS}T (out), 2 VSS, 3 ~{M}R (in), 4 VCC2 (in), 5 VCC1 (in)

## STMIPID02
designator U?
pins: A1 DATA1P2 (in), A2 TCK (in), A3 TDO (out), A4 POR_TST (in), A5 D10 (out), A6 EXT_CLK (in), A7 LDO_TST (in), B1 DATA1IN2 (in), B2 CLKP2 (in), B3 TDI (in), B4 POR_SGN (io), B5 D11 (out), B6 D8 (out), B7 D9 (out), C1 DATA2P1 (in), C2 CLKN2 (in), C3 TMS (in), C4 VDDE_1V8 (power), C5 GNDE (power), C6 D6 (out), C7 D7 (out), D1 CLKP1 (in), D2 DATA2N1 (in), D3 GNDE (power), D4 VDD_1V2 (power), D5 GND_1V2 (power), D6 D4 (out), D7 D5 (out), E1 DATA1P1 (in), E2 CLKN1 (in), E3 GND_PHY (power), E4 ERROR (out), E5 VSYNC (out), E6 D3 (out), E7 D2 (out), F1 DATA1N1 (in), F2 VDDOUT_LDO (power), F3 XSDN (in), F4 INT (out), F5 SCL (in), F6 GNDE (power), F7 D1 (out), G1 VDDIN_LDO (power), G2 GNDE_LDO (power), G3 VDDE_1V8 (power), G4 HSYNC (out), G5 PCLK (out), G6 SDA (io), G7 D0 (out)

## STMPE811QTR
designator U?
pins: 1 Y-, 2 INT (out), 3 A0-DATA_OUT, 4 SCLK, 5 SDAT, 6 VCC, 7 DATA_IN, 8 IN0, 9 IN1, 10 GND, 11 IN2, 12 IN3, 13 X+, 14 VIO, 15 Y+, 16 X-

## STMPE1600QTR
designator U?
pins: 1 GPIO0, 2 GPIO1, 3 GPIO2, 4 GPIO3, 5 GPIO4, 6 GPIO5, 7 GPIO6, 8 GPIO7, 9 GND, 10 GPIO8, 11 GPIO9, 12 GPIO10, 13 GPIO11, 14 GPIO12, 15 GPIO13, 16 GPIO14, 17 GPIO15, 18 A0, 19 I2C_SCL, 20 I2C_SDA, 21 VCC, 22 INT, 23 A1, 24 A2

## STMPE1801BJR
designator U?
pins: A1 RSTB, A2 GPIO14, A3 GPIO9, A4 GPIO2, A5 GPIO7, B1 VCC, B2 GPIO15, B3 GPIO10, B4 NC, B5 GPIO6, C1 I2C_SDA, C2 GPIO16, C3 GPIO11, C4 GPIO1, C5 GPIO5, D1 I2C_SCL, D2 GPIO17, D3 GPIO12, D4 GPIO0, D5 GPIO4, E1 INTB, E2 GND, E3 GPIO13, E4 GPIO8, E5 GPIO3

## STMPS2141MTR
designator U?
pins: 1 GND, 2 IN, 3 IN, 4 ~{ON}, 5 ~{FAULT}, 6 OUT, 7 OUT, 8 OUT, 9 EP-GND

## STMPS2141STR
designator U?
pins: 1 OUT, 2 GND, 3 ~{FAULT}, 4 ~{EN}, 5 IN

## STMPS2151STR
designator U?
pins: 1 OUT, 2 GND, 3 ~{FAULT}, 4 EN, 5 IN

## STMPS2161STR
designator U?
pins: 1 OUT, 2 GND, 3 ~{FAULT} (out), 4 EN_N (in), 5 IN

## STMPS2171STR
designator U?
pins: 1 OUT, 2 GND, 3 ~{FAULT}, 4 EN, 5 IN

## STMPS2252MTR
designator U?
pins: 1 GND, 2 IN, 3 EN1, 4 EN2, 5 notOC2, 6 OUT2, 7 OUT1, 8 notOC1

## STN4NF20L
designator Q?
pins: 1 G, 2 D, 3 S, 4 D

## STN790A
designator Q?
pins: 1 B, 2 C, 3 E, 4 C

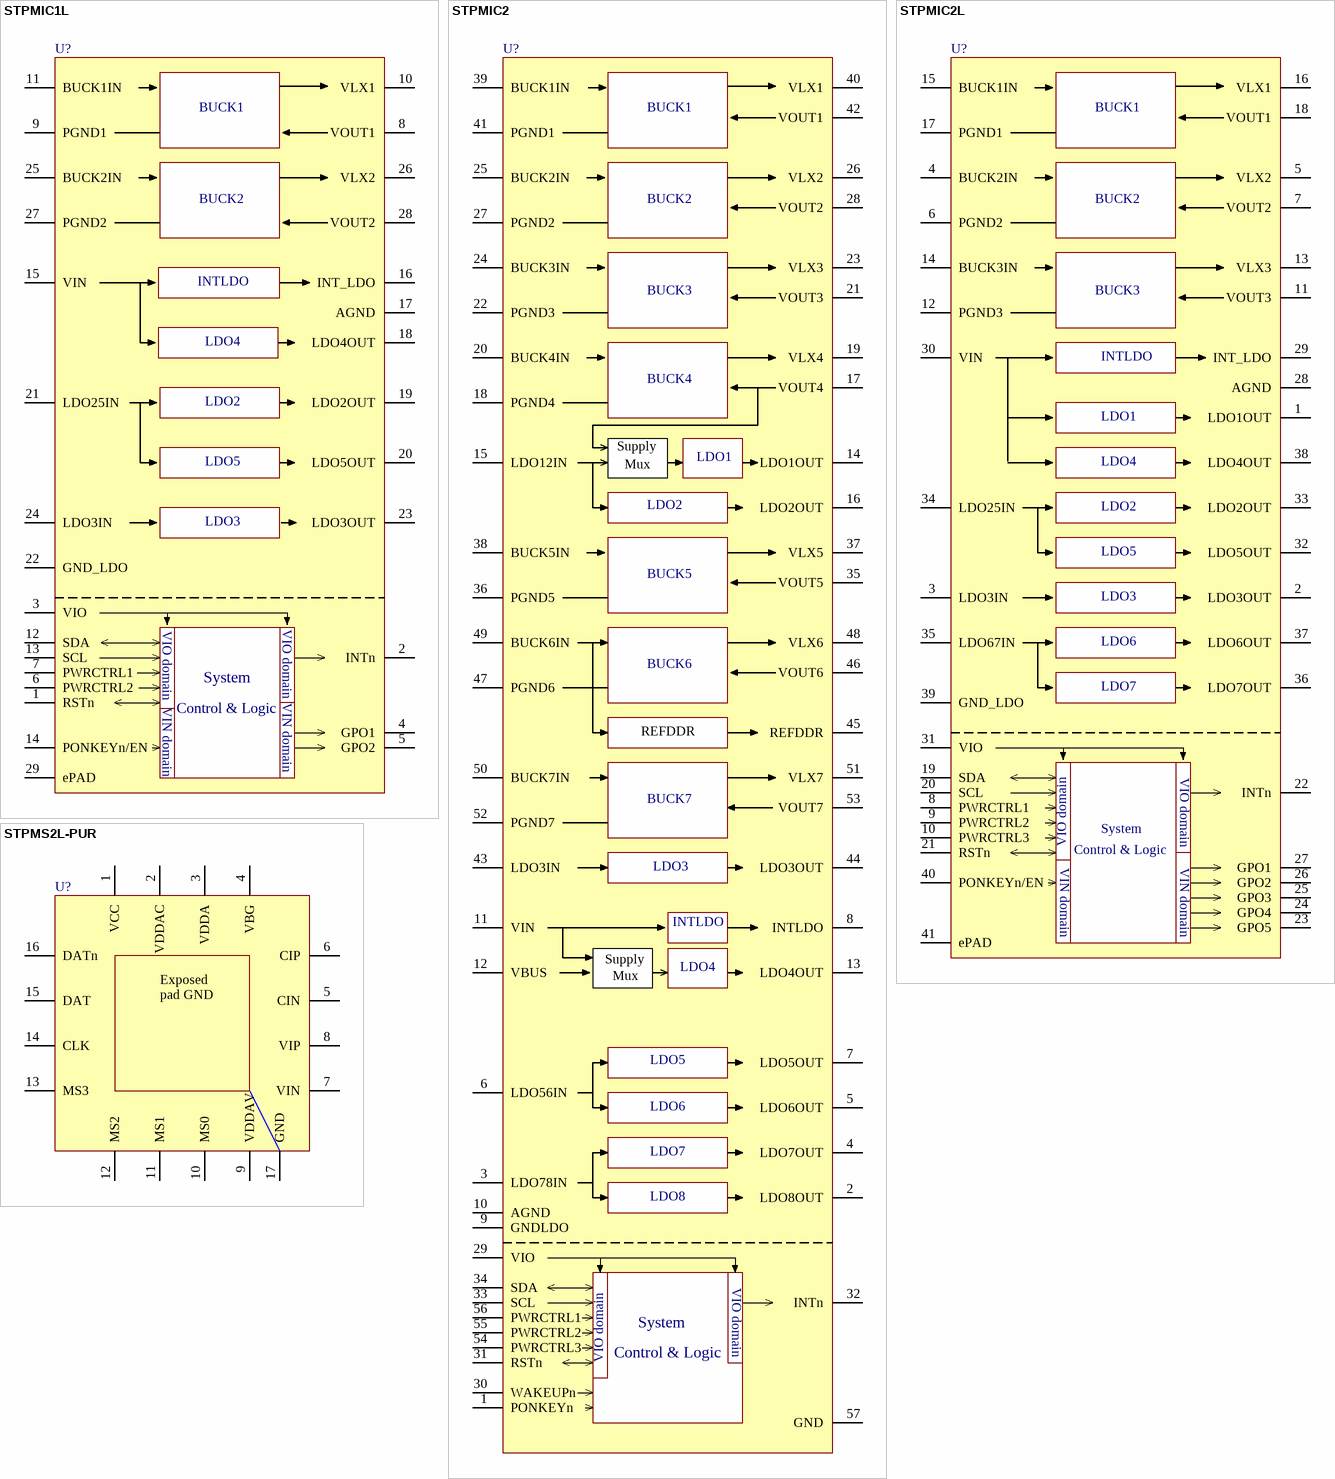
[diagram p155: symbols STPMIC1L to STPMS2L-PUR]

## STPMIC1L
designator U?
pins: 1 RSTn, 2 INTn, 3 VIO, 4 GPO1, 5 GPO2, 6 PWRCTRL2, 7 PWRCTRL1, 8 VOUT1, 9 PGND1, 10 VLX1, 11 BUCK1IN, 12 SDA, 13 SCL, 14 PONKEYn/EN, 15 VIN, 16 INT_LDO, 17 AGND, 18 LDO4OUT, 19 LDO2OUT, 20 LDO5OUT, 21 LDO25IN, 22 GND_LDO, 23 LDO3OUT, 24 LDO3IN, 25 BUCK2IN, 26 VLX2, 27 PGND2, 28 VOUT2, 29 ePAD

## STPMIC2
designator U?
pins: 1 PONKEYn, 2 LDO8OUT, 3 LDO78IN, 4 LDO7OUT, 5 LDO6OUT, 6 LDO56IN, 7 LDO5OUT, 8 INTLDO, 9 GNDLDO, 10 AGND, 11 VIN, 12 VBUS, 13 LDO4OUT, 14 LDO1OUT, 15 LDO12IN, 16 LDO2OUT, 17 VOUT4, 18 PGND4, 19 VLX4, 20 BUCK4IN, 21 VOUT3, 22 PGND3, 23 VLX3, 24 BUCK3IN, 25 BUCK2IN, 26 VLX2, 27 PGND2, 28 VOUT2, 29 VIO, 30 WAKEUPn, 31 RSTn, 32 INTn, 33 SCL, 34 SDA, 35 VOUT5, 36 PGND5, 37 VLX5, 38 BUCK5IN, 39 BUCK1IN, 40 VLX1, 41 PGND1, 42 VOUT1, 43 LDO3IN, 44 LDO3OUT, 45 REFDDR, 46 VOUT6, 47 PGND6, 48 VLX6, 49 BUCK6IN, 50 BUCK7IN, 51 VLX7, 52 PGND7, 53 VOUT7, 54 PWRCTRL3, 55 PWRCTRL2, 56 PWRCTRL1, 57 GND

## STPMIC2L
designator U?
pins: 1 LDO1OUT, 2 LDO3OUT, 3 LDO3IN, 4 BUCK2IN, 5 VLX2, 6 PGND2, 7 VOUT2, 8 PWRCTRL1, 9 PWRCTRL2, 10 PWRCTRL3, 11 VOUT3, 12 PGND3, 13 VLX3, 14 BUCK3IN, 15 BUCK1IN, 16 VLX1, 17 PGND1, 18 VOUT1, 19 SDA, 20 SCL, 21 RSTn, 22 INTn, 23 GPO5, 24 GPO4, 25 GPO3, 26 GPO2, 27 GPO1, 28 AGND, 29 INT_LDO, 30 VIN, 31 VIO, 32 LDO5OUT, 33 LDO2OUT, 34 LDO25IN, 35 LDO67IN, 36 LDO7OUT, 37 LDO6OUT, 38 LDO4OUT, 39 GND_LDO, 40 PONKEYn/EN, 41 ePAD

## STPMS2L-PUR
designator U?
pins: 1 VCC, 2 VDDAC, 3 VDDA, 4 VBG, 5 CIN, 6 CIP, 7 VIN, 8 VIP, 9 VDDAV, 10 MS0, 11 MS1, 12 MS2, 13 MS3, 14 CLK, 15 DAT, 16 DATn, 17 GND

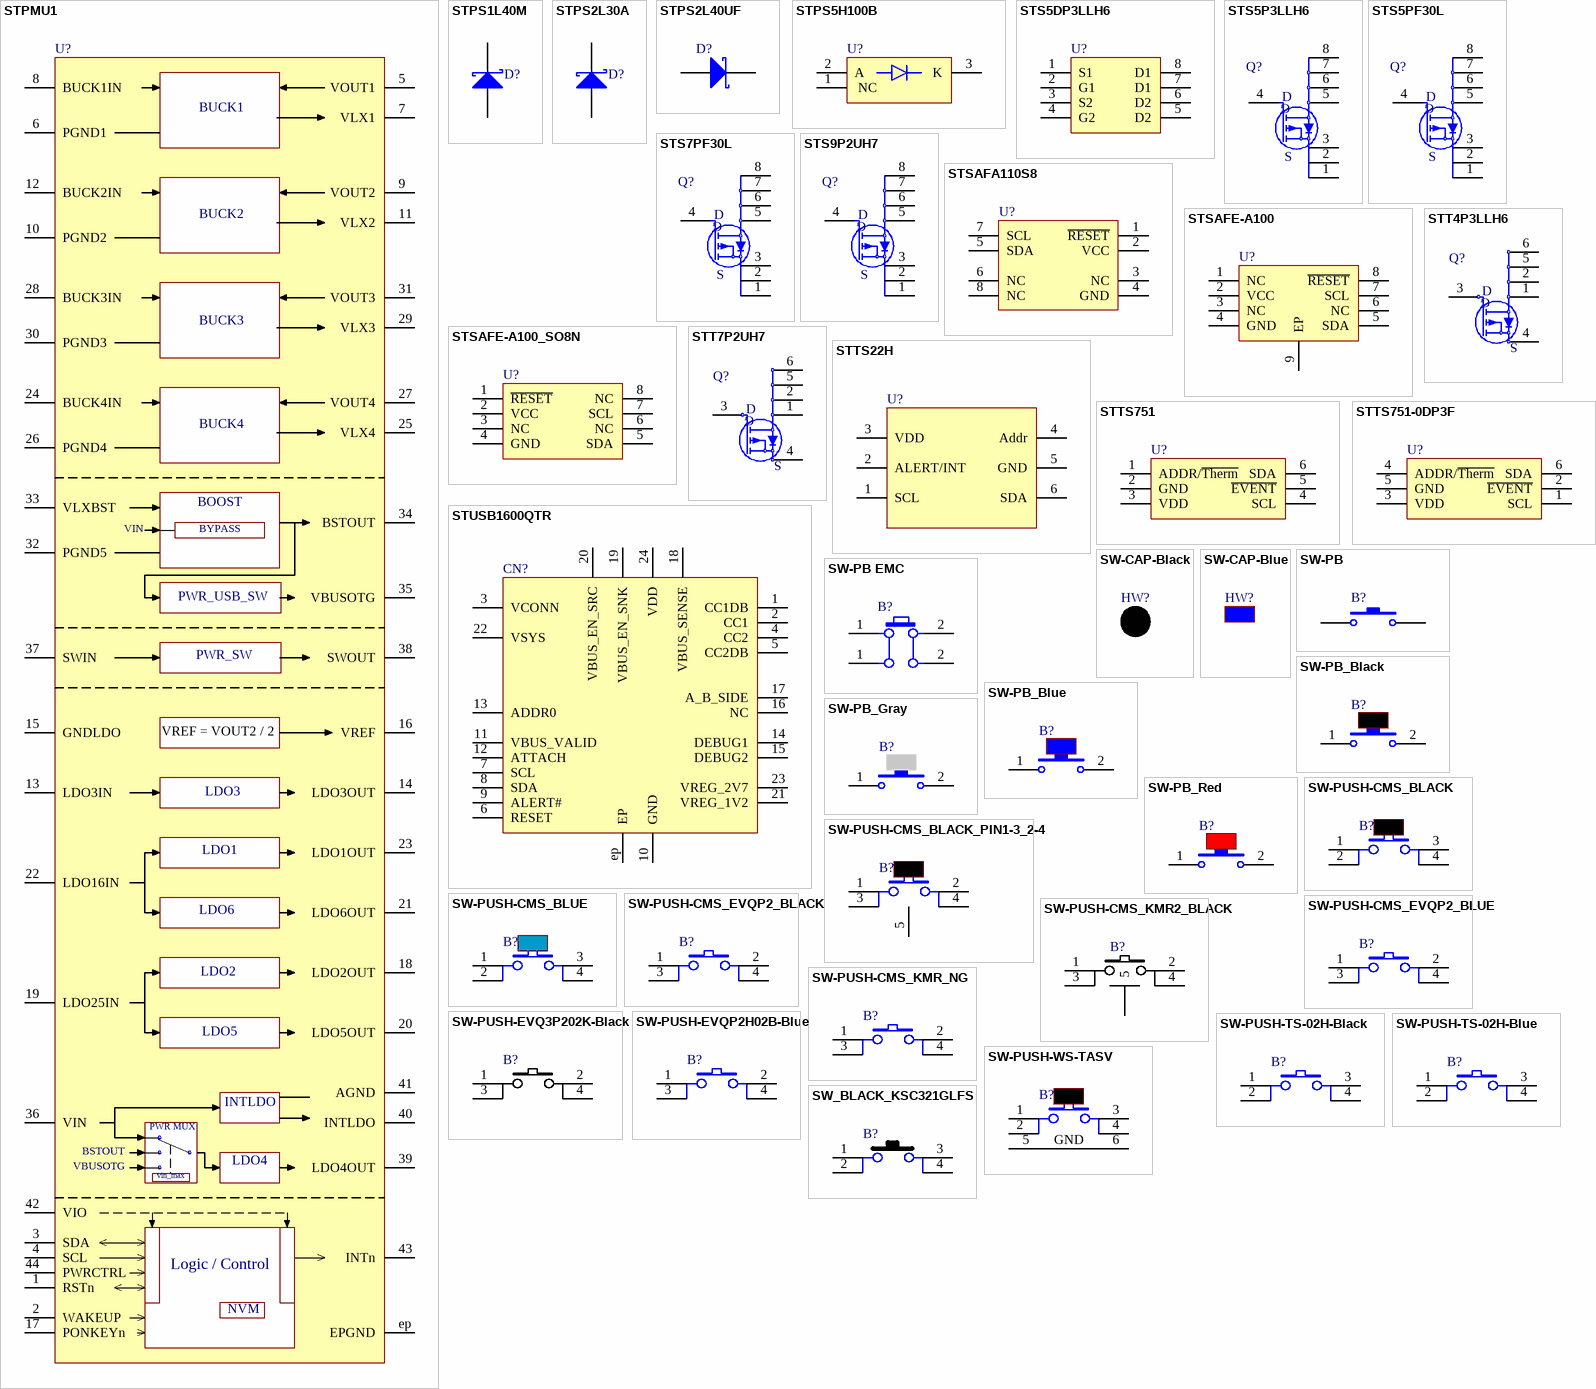
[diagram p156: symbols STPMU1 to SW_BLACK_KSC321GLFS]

## STPMU1
designator U?
pins: 1 RSTn, 2 WAKEUP, 3 SDA, 4 SCL, 5 VOUT1, 6 PGND1, 7 VLX1, 8 BUCK1IN, 9 VOUT2, 10 PGND2, 11 VLX2, 12 BUCK2IN, 13 LDO3IN, 14 LDO3OUT, 15 GNDLDO, 16 VREF, 17 PONKEYn, 18 LDO2OUT, 19 LDO25IN, 20 LDO5OUT, 21 LDO6OUT, 22 LDO16IN, 23 LDO1OUT, 24 BUCK4IN, 25 VLX4, 26 PGND4, 27 VOUT4, 28 BUCK3IN, 29 VLX3, 30 PGND3, 31 VOUT3, 32 PGND5, 33 VLXBST, 34 BSTOUT, 35 VBUSOTG, 36 VIN, 37 SWIN, 38 SWOUT, 39 LDO4OUT, 40 INTLDO, 41 AGND, 42 VIO, 43 INTn, 44 PWRCTRL, ep EPGND

## STPS1L40M
designator D?
pins: 1 A, 2 K

## STPS2L30A
designator D?
pins: 1 A, 2 K

## STPS2L40UF
designator D?
pins: 1 A, 2 K

## STPS5H100B
designator U?
pins: 1  NC, 2 A, 3 K

## STS5DP3LLH6
designator U?
pins: 1 S1, 2 G1, 3 S2, 4 G2, 5 D2, 6 D2, 7 D1, 8 D1

## STS5P3LLH6
designator Q?
pins: 1 S, 2 S, 3 S, 4 G, 5 D, 6 D, 7 D, 8 D

## STS5PF30L
designator Q?
pins: 1 S, 2 S, 3 S, 4 G, 5 D, 6 D, 7 D, 8 D

## STS7PF30L
designator Q?
pins: 1 S, 2 S, 3 S, 4 G, 5 D, 6 D, 7 D, 8 D

## STS9P2UH7
designator Q?
pins: 1 S, 2 S, 3 S, 4 G, 5 D, 6 D, 7 D, 8 D

## STSAFA110S8
designator U?
pins: 1 ~{RESET}, 2 VCC, 3 NC, 4 GND, 5 SDA, 6 NC, 7 SCL, 8 NC

## STSAFE-A100
designator U?
pins: 1 NC, 2 VCC, 3 NC, 4 GND, 5 SDA, 6 NC, 7 SCL, 8 ~{RESET}, 9 EP

## STSAFE-A100_SO8N
designator U?
pins: 1 ~{RESET}, 2 VCC, 3 NC, 4 GND, 5 SDA, 6 NC, 7 SCL, 8 NC

## STT4P3LLH6
designator Q?
pins: 1 S, 2 S, 3 G, 4 S, 5 D, 6 D

## STT7P2UH7
designator Q?
pins: 1 S, 2 S, 3 G, 4 S, 5 D, 6 D

## STTS22H
designator U?
pins: 1 SCL, 2 ALERT/INT, 3 VDD, 4 Addr, 5 GND, 6 SDA

## STTS751
designator U?
pins: 1 ADDR/~{Therm}, 2 GND, 3 VDD, 4 SCL, 5 ~{EVENT}, 6 SDA

## STTS751-0DP3F
designator U?
pins: 1 SCL, 2 ~{EVENT}, 3 VDD, 4 ADDR/~{Therm}, 5 GND, 6 SDA

## STUSB1600QTR
designator CN?
pins: 1 CC1DB "Dead battery enable on CC1 pin", 2 CC1 "Type-C configuration channel 1", 3 VCONN "Power input for active plug", 4 CC2 "Type-C configuration channel 2", 5 CC2DB "Dead battery enable on CC2 pin", 6 RESET "Reset input (active high)", 7 SCL "I2C clock input", 8 SDA "I2C data input/output, active low open drain", 9 ALERT# "I2C interrupt, active low open drain", 10 GND "Ground", 11 VBUS_VALID "VBUS detection, active low open drain", 12 ATTACH "Attachment detection, active low open drain", 13 ADDR0 ""I²C device address setting (see", 14 DEBUG1 "Debug accessory device detection in sink power role, active low open drain", 15 DEBUG2 "Debug accessory device detection in source power role, active low open drain", 16 NC "—", 17 A_B_SIDE "Cable orientation, active low open drain", 18 VBUS_SENSE "VBUS voltage monitoring and discharge path", 19 VBUS_EN_SNK "VBUS sink power path enable, active low open drain", 20 VBUS_EN_SRC "VBUS source power path enable, active low open drain", 21 VREG_1V2 "1.2 V internal regulator output", 22 VSYS "Power supply from system", 23 VREG_2V7 "2.7 V internal regulator output", 24 VDD "Power supply from USB power line", ep EP "Ground"

## SW-CAP-Black
designator HW?  (mechanical)

## SW-CAP-Blue
designator HW?  (mechanical)

## SW-PB
designator B?
pins: 1, 2

## SW-PB EMC
designator B?
pins: 1 A0, 1 A1, 2, 2 B1

## SW-PB_Black
designator B?
pins: 1, 2

## SW-PB_Blue
designator B?
pins: 1, 2

## SW-PB_Gray
designator B?
pins: 1, 2

## SW-PB_Red
designator B?
pins: 1, 2

## SW-PUSH-CMS_BLACK
designator B?
pins: 1, 2, 3, 4

## SW-PUSH-CMS_BLACK_PIN1-3_2-4
designator B?
pins: 1, 2, 3, 4, 5 GND

## SW-PUSH-CMS_BLUE
designator B?
pins: 1, 2, 3, 4

## SW-PUSH-CMS_EVQP2_BLACK
designator B?
pins: 1, 2, 3, 4

## SW-PUSH-CMS_EVQP2_BLUE
designator B?
pins: 1, 2, 3, 4

## SW-PUSH-CMS_KMR2_BLACK
designator B?
pins: 1, 2, 3, 4, 5

## SW-PUSH-CMS_KMR_NG
designator B?
pins: 1, 2, 3, 4

## SW-PUSH-EVQ3P202K-Black
designator B?
pins: 1, 2, 3, 4

## SW-PUSH-EVQP2H02B-Blue
designator B?
pins: 1, 2, 3, 4

## SW-PUSH-TS-02H-Black
designator B?
pins: 1, 2, 3, 4

## SW-PUSH-TS-02H-Blue
designator B?
pins: 1, 2, 3, 4

## SW-PUSH-WS-TASV
designator B?
pins: 1, 2, 3, 4, 5, 6

## SW_BLACK_KSC321GLFS
designator B?
pins: 1, 2, 3, 4

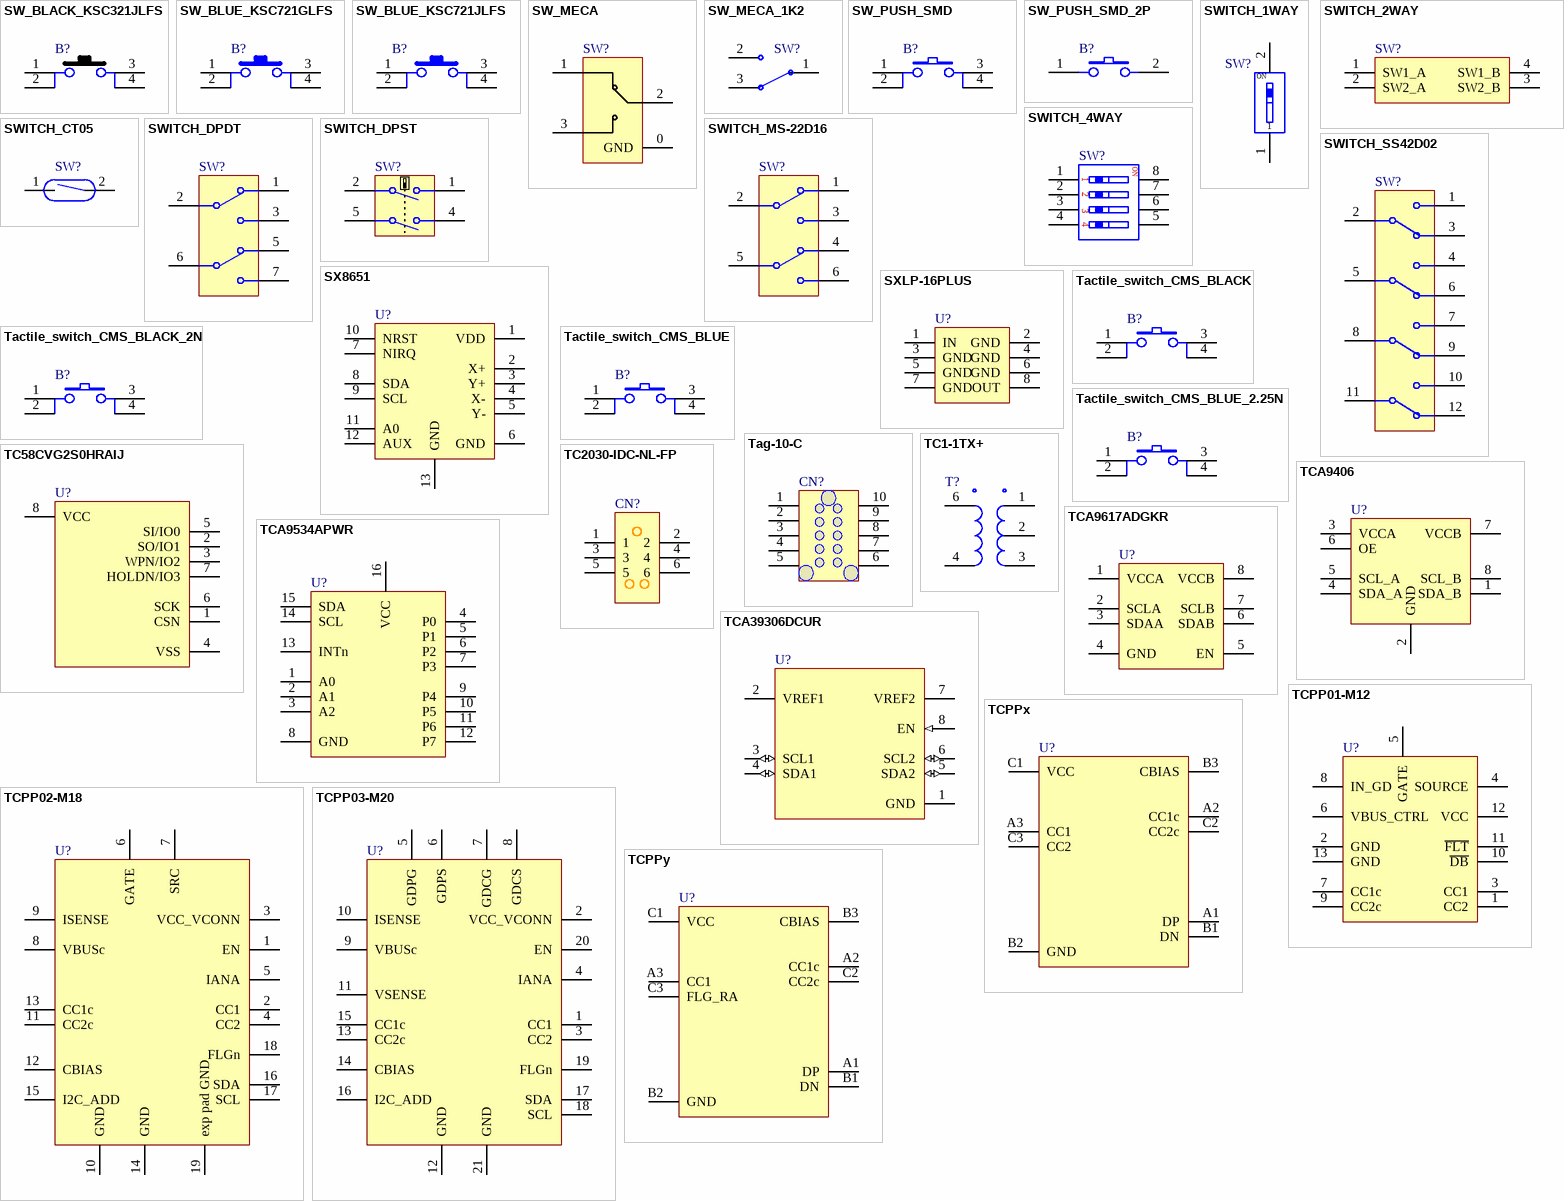
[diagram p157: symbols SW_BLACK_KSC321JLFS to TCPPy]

## SW_BLACK_KSC321JLFS
designator B?
pins: 1, 2, 3, 4

## SW_BLUE_KSC721GLFS
designator B?
pins: 1, 2, 3, 4

## SW_BLUE_KSC721JLFS
designator B?
pins: 1, 2, 3, 4

## SW_MECA
designator SW?
pins: 0 GND, 1, 2, 3

## SW_MECA_1K2
designator SW?
pins: 1, 2, 3

## SW_PUSH_SMD
designator B?
pins: 1, 2, 3, 4

## SW_PUSH_SMD_2P
designator B?
pins: 1, 2

## SWITCH_1WAY
designator SW?
pins: 1, 2

## SWITCH_2WAY
designator SW?
pins: 1 SW1_A, 2 SW2_A, 3 SW2_B, 4 SW1_B

## SWITCH_4WAY
designator SW?
pins: 1, 2, 3, 4, 5, 6, 7, 8

## SWITCH_CT05
designator SW?
pins: 1, 2

## SWITCH_DPDT
designator SW?
pins: 1, 2, 3, 5, 6, 7

## SWITCH_DPST
designator SW?
pins: 1, 2, 4, 5

## SWITCH_MS-22D16
designator SW?
pins: 1, 2, 3, 4, 5, 6

## SWITCH_SS42D02
designator SW?
pins: 1, 2, 3, 4, 5, 6, 7, 8, 9, 10, 11, 12

## SX8651
designator U?
pins: 1 VDD, 2 X+, 3 Y+, 4 X-, 5 Y-, 6 GND, 7 NIRQ, 8 SDA, 9 SCL, 10 NRST, 11 A0, 12 AUX, 13 GND

## SXLP-16PLUS
designator U?
pins: 1 IN, 2 GND, 3 GND, 4 GND, 5 GND, 6 GND, 7 GND, 8 OUT

## Tactile_switch_CMS_BLACK
designator B?
pins: 1, 2, 3, 4

## Tactile_switch_CMS_BLACK_2N
designator B?
pins: 1, 2, 3, 4

## Tactile_switch_CMS_BLUE
designator B?
pins: 1, 2, 3, 4

## Tactile_switch_CMS_BLUE_2.25N
designator B?
pins: 1, 2, 3, 4

## Tag-10-C
designator CN?  (no BOM)
pins: 1, 2, 3, 4, 5, 6, 7, 8, 9, 10

## TC1-1TX+
designator T?
pins: 1, 2, 3, 4, 6

## TC58CVG2S0HRAIJ
designator U?
pins: 1 CSN, 2 SO/IO1, 3 WPN/IO2, 4 VSS, 5 SI/IO0, 6 SCK, 7 HOLDN/IO3, 8 VCC

## TC2030-IDC-NL-FP
designator CN?  (no BOM)
pins: 1, 2, 3, 4, 5, 6

## TCA9406
designator U?
pins: 1 SDA_B, 2 GND, 3 VCCA, 4 SDA_A, 5 SCL_A, 6 OE, 7 VCCB, 8 SCL_B

## TCA9534APWR
designator U?
pins: 1 A0, 2 A1, 3 A2, 4 P0, 5 P1, 6 P2, 7 P3, 8 GND, 9 P4, 10 P5, 11 P6, 12 P7, 13 INTn, 14 SCL, 15 SDA, 16 VCC (power)

## TCA9617ADGKR
designator U?
pins: 1 VCCA, 2 SCLA, 3 SDAA, 4 GND, 5 EN, 6 SDAB, 7 SCLB, 8 VCCB

## TCA39306DCUR
designator U?
pins: 1 GND (power), 2 VREF1 (power), 3 SCL1 (io), 4 SDA1 (io), 5 SDA2 (io), 6 SCL2 (io), 7 VREF2 (power), 8 EN (in)

## TCPP01-M12
designator U?
pins: 1 CC2, 2 GND, 3 CC1, 4 SOURCE, 5 GATE, 6 VBUS_CTRL, 7 CC1c, 8 IN_GD, 9 CC2c, 10 ~{DB}, 11 ~{FLT}, 12 VCC, 13 GND

## TCPP02-M18
designator U?
pins: 1 EN, 2 CC1, 3 VCC_VCONN, 4 CC2, 5 IANA, 6 GATE, 7 SRC, 8 VBUSc, 9 ISENSE, 10 GND, 11 CC2c, 12 CBIAS, 13 CC1c, 14 GND, 15 I2C_ADD, 16 SDA, 17 SCL, 18 FLGn, 19 exp pad GND

## TCPP03-M20
designator U?
pins: 1 CC1, 2 VCC_VCONN, 3 CC2, 4 IANA, 5 GDPG, 6 GDPS, 7 GDCG, 8 GDCS, 9 VBUSc, 10 ISENSE, 11 VSENSE, 12 GND, 13 CC2c, 14 CBIAS, 15 CC1c, 16 I2C_ADD, 17 SDA, 18 SCL, 19 FLGn, 20 EN, 21 GND

## TCPPx
designator U?
pins: A1 DP, A2 CC1c, A3 CC1, B1 DN, B2 GND, B3 CBIAS, C1 VCC (power), C2 CC2c, C3 CC2

## TCPPy
designator U?
pins: A1 DP, A2 CC1c, A3 CC1, B1 DN, B2 GND, B3 CBIAS, C1 VCC (power), C2 CC2c, C3 FLG_RA

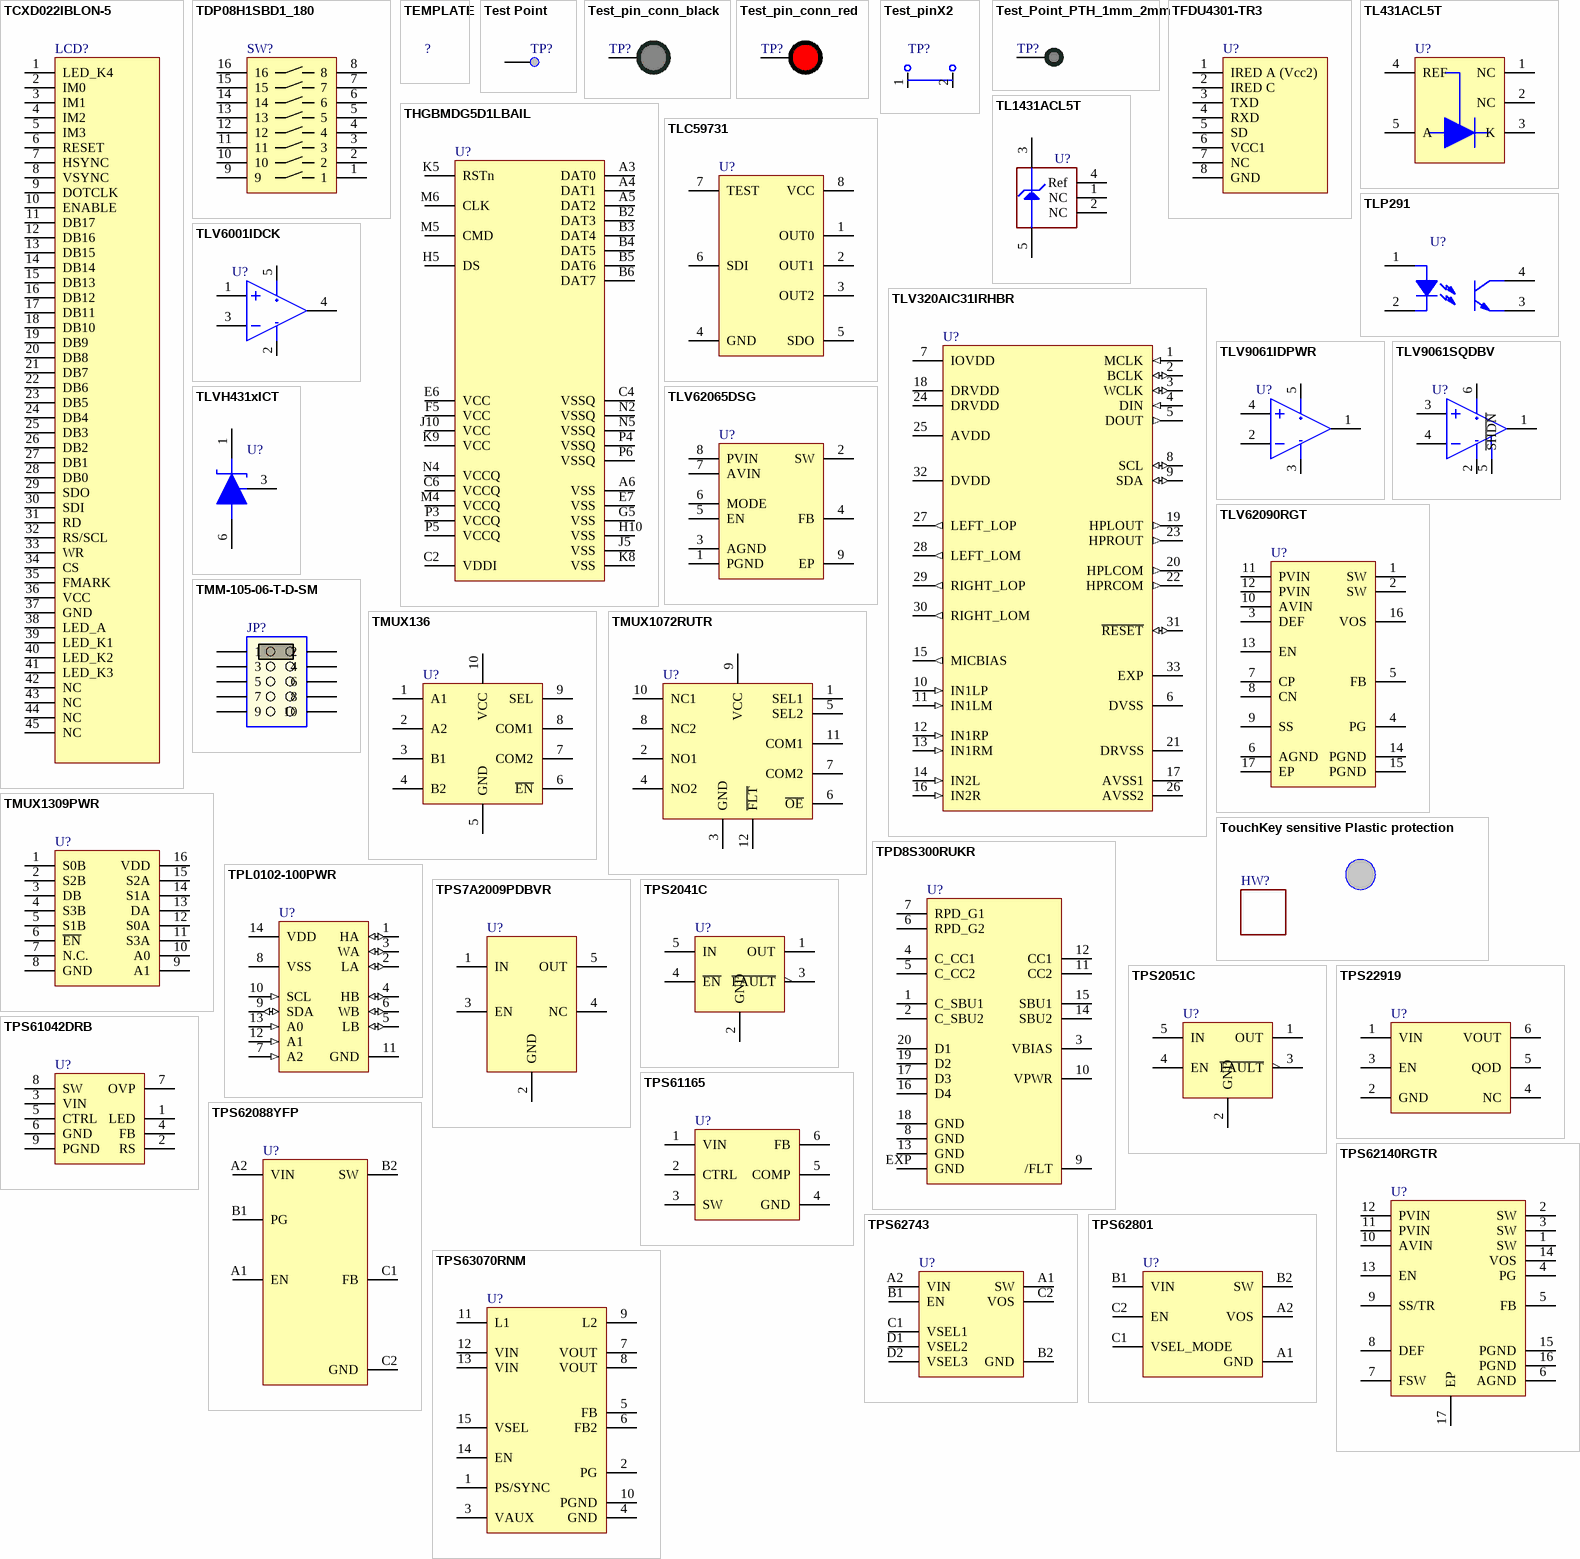
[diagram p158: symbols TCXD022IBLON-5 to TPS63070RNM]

## TCXD022IBLON-5
designator LCD?
pins: 1 LED_K4 , 2 IM0, 3 IM1, 4 IM2, 5 IM3, 6 RESET, 7 HSYNC, 8 VSYNC, 9 DOTCLK, 10 ENABLE, 11 DB17, 12 DB16, 13 DB15, 14 DB14, 15 DB13, 16 DB12, 17 DB11, 18 DB10, 19 DB9, 20 DB8, 21 DB7, 22 DB6, 23 DB5, 24 DB4, 25 DB3, 26 DB2, 27 DB1, 28 DB0, 29 SDO, 30 SDI, 31 RD, 32 RS/SCL, 33 WR, 34 CS, 35 FMARK, 36 VCC, 37 GND, 38 LED_A, 39 LED_K1, 40 LED_K2, 41 LED_K3, 42 NC, 43 NC, 44 NC, 45 NC

## TDP08H1SBD1_180
designator SW?
pins: 1, 2, 3, 4, 5, 6, 7, 8, 9, 10, 11, 12, 13, 14, 15, 16

## TEMPLATE
designator ?

## Test Point
designator TP?  (no BOM)
pins: 1

## Test_pin_conn_black
designator TP?
pins: 1

## Test_pin_conn_red
designator TP?
pins: 1

## Test_pinX2
designator TP?  (no BOM)
pins: 1, 2

## Test_Point_PTH_1mm_2mm
designator TP?  (no BOM)
pins: 1

## TFDU4301-TR3
designator U?
pins: 1 IRED A (Vcc2), 2 IRED C, 3 TXD, 4 RXD, 5 SD, 6 VCC1, 7 NC, 8 GND

## THGBMDG5D1LBAIL
designator U?
pins: A3 DAT0, A4 DAT1, A5 DAT2, A6 VSS, B2 DAT3, B3 DAT4, B4 DAT5, B5 DAT6, B6 DAT7, C2 VDDI, C4 VSSQ, C6 VCCQ, E6 VCC, E7 VSS, F5 VCC, G5 VSS, H5 DS, H10 VSS, J5 VSS, J10 VCC, K5 RSTn, K8 VSS, K9 VCC, M4 VCCQ, M5 CMD, M6 CLK, N2 VSSQ, N4 VCCQ, N5 VSSQ, P3 VCCQ, P4 VSSQ, P5 VCCQ, P6 VSSQ

## TL431ACL5T
designator U?
pins: 1 NC, 2 NC, 3 K, 4 REF, 5 A

## TL1431ACL5T
designator U?
pins: 1 NC, 2 NC, 3 Cathode, 4 Ref, 5 Anode

## TLC59731
designator U?
pins: 1 OUT0, 2 OUT1, 3 OUT2, 4 GND, 5 SDO, 6 SDI, 7 TEST, 8 VCC

## TLP291
designator U?
pins: 1, 2, 3, 4

## TLV320AIC31IRHBR
designator U?
pins: 1 MCLK (in), 2 BCLK (io), 3 WCLK (io), 4 DIN (in), 5 DOUT (out), 6 DVSS (power), 7 IOVDD (power), 8 SCL (io), 9 SDA (io), 10 IN1LP (in), 11 IN1LM (in), 12 IN1RP (in), 13 IN1RM (in), 14 IN2L (in), 15 MICBIAS (out), 16 IN2R (in), 17 AVSS1 (power), 18 DRVDD (power), 19 HPLOUT (out), 20 HPLCOM (out), 21 DRVSS (power), 22 HPRCOM (out), 23 HPROUT (out), 24 DRVDD (power), 25 AVDD (power), 26 AVSS2 (power), 27 LEFT_LOP (out), 28 LEFT_LOM (out), 29 RIGHT_LOP (out), 30 RIGHT_LOM (out), 31 ~{RESET} (io), 32 DVDD (power), 33 EXP

## TLV6001IDCK
designator U?
pins: 1 +IN, 2 V- (power), 3 -IN, 4 VOUT (hiz), 5 V+ (power)

## TLV9061IDPWR
designator U?
pins: 1 VOUT (hiz), 2 -IN, 3 V- (power), 4 +IN, 5 V+ (power)

## TLV9061SQDBV
designator U?
pins: 1 VOUT (hiz), 2 V- (power), 3 +IN, 4 -IN, 5 ~{SHDN} (power), 6 V+ (power)

## TLV62065DSG
designator U?
pins: 1 PGND, 2 SW, 3 AGND, 4 FB, 5 EN, 6 MODE, 7 AVIN, 8 PVIN, 9 EP

## TLV62090RGT
designator U?
pins: 1 SW, 2 SW, 3 DEF, 4 PG, 5 FB, 6 AGND, 7 CP, 8 CN, 9 SS, 10 AVIN, 11 PVIN, 12 PVIN, 13 EN, 14 PGND, 15 PGND, 16 VOS, 17 EP

## TLVH431xICT
designator U?
pins: 1 K, 3 REF, 6 A

## TMM-105-06-T-D-SM
designator JP?
pins: 1, 2, 3, 4, 5, 6, 7, 8, 9, 10

## TMUX136
designator U?
pins: 1 A1, 2 A2, 3 B1, 4 B2, 5 GND, 6 ~{EN}, 7 COM2, 8 COM1, 9 SEL, 10 VCC (power)

## TMUX1072RUTR
designator U?
pins: 1 SEL1, 2 NO1, 3 GND, 4 NO2, 5 SEL2, 6 ~{OE}, 7 COM2, 8 NC2, 9 VCC (power), 10 NC1, 11 COM1, 12 ~{FLT}

## TMUX1309PWR
designator U?
pins: 1 S0B, 2 S2B, 3 DB, 4 S3B, 5 S1B, 6 ~{EN}, 7 N.C., 8 GND, 9 A1, 10 A0, 11 S3A, 12 S0A, 13 DA, 14 S1A, 15 S2A, 16 VDD

## TouchKey sensitive Plastic protection
designator HW?  (mechanical)

## TPD8S300RUKR
designator U?
pins: 1 C_SBU1, 2 C_SBU2, 3 VBIAS, 4 C_CC1, 5 C_CC2, 6 RPD_G2, 7 RPD_G1, 8 GND, 9 /FLT, 10 VPWR, 11 CC2, 12 CC1, 13 GND, 14 SBU2, 15 SBU1, 16 D4, 17 D3, 18 GND, 19 D2, 20 D1, EXP GND

## TPL0102-100PWR
designator U?
pins: 1 HA (io), 2 LA (io), 3 WA (io), 4 HB (io), 5 LB (io), 6 WB (io), 7 A2 (in), 8 VSS (power), 9 SDA (io), 10 SCL (in), 11 GND (power), 12 A1 (in), 13 A0 (in), 14 VDD (power)

## TPS7A2009PDBVR
designator U?
pins: 1 IN, 2 GND, 3 EN, 4 NC, 5 OUT

## TPS2041C
designator U?
pins: 1 OUT, 2 GND, 3 ~{FAULT}, 4 ~{EN}, 5 IN

## TPS2051C
designator U?
pins: 1 OUT, 2 GND, 3 ~{FAULT}, 4 EN, 5 IN

## TPS22919
designator U?
pins: 1 VIN, 2 GND, 3 EN, 4 NC, 5 QOD, 6 VOUT

## TPS61042DRB
designator U?
pins: 1 LED, 2 RS, 3 VIN, 4 FB, 5 CTRL, 6 GND, 7 OVP, 8 SW, 9 PGND

## TPS61165
designator U?
pins: 1 VIN, 2 CTRL, 3 SW, 4 GND, 5 COMP, 6 FB

## TPS62088YFP
designator U?
pins: A1 EN, A2 VIN, B1 PG, B2 SW, C1 FB, C2 GND

## TPS62140RGTR
designator U?
pins: 1 SW, 2 SW, 3 SW, 4 PG, 5 FB, 6 AGND, 7 FSW, 8 DEF, 9 SS/TR, 10 AVIN, 11 PVIN, 12 PVIN, 13 EN, 14 VOS, 15 PGND, 16 PGND, 17 EP

## TPS62743
designator U?
pins: A1 SW, A2 VIN, B1 EN, B2 GND, C1 VSEL1, C2 VOS, D1 VSEL2, D2 VSEL3

## TPS62801
designator U?
pins: A1 GND, A2 VOS, B1 VIN, B2 SW, C1 VSEL_MODE, C2 EN

## TPS63070RNM
designator U?
pins: 1 PS/SYNC, 2 PG, 3 VAUX, 4 GND, 5 FB, 6 FB2, 7 VOUT, 8 VOUT, 9 L2, 10 PGND, 11 L1, 12 VIN, 13 VIN, 14 EN, 15 VSEL

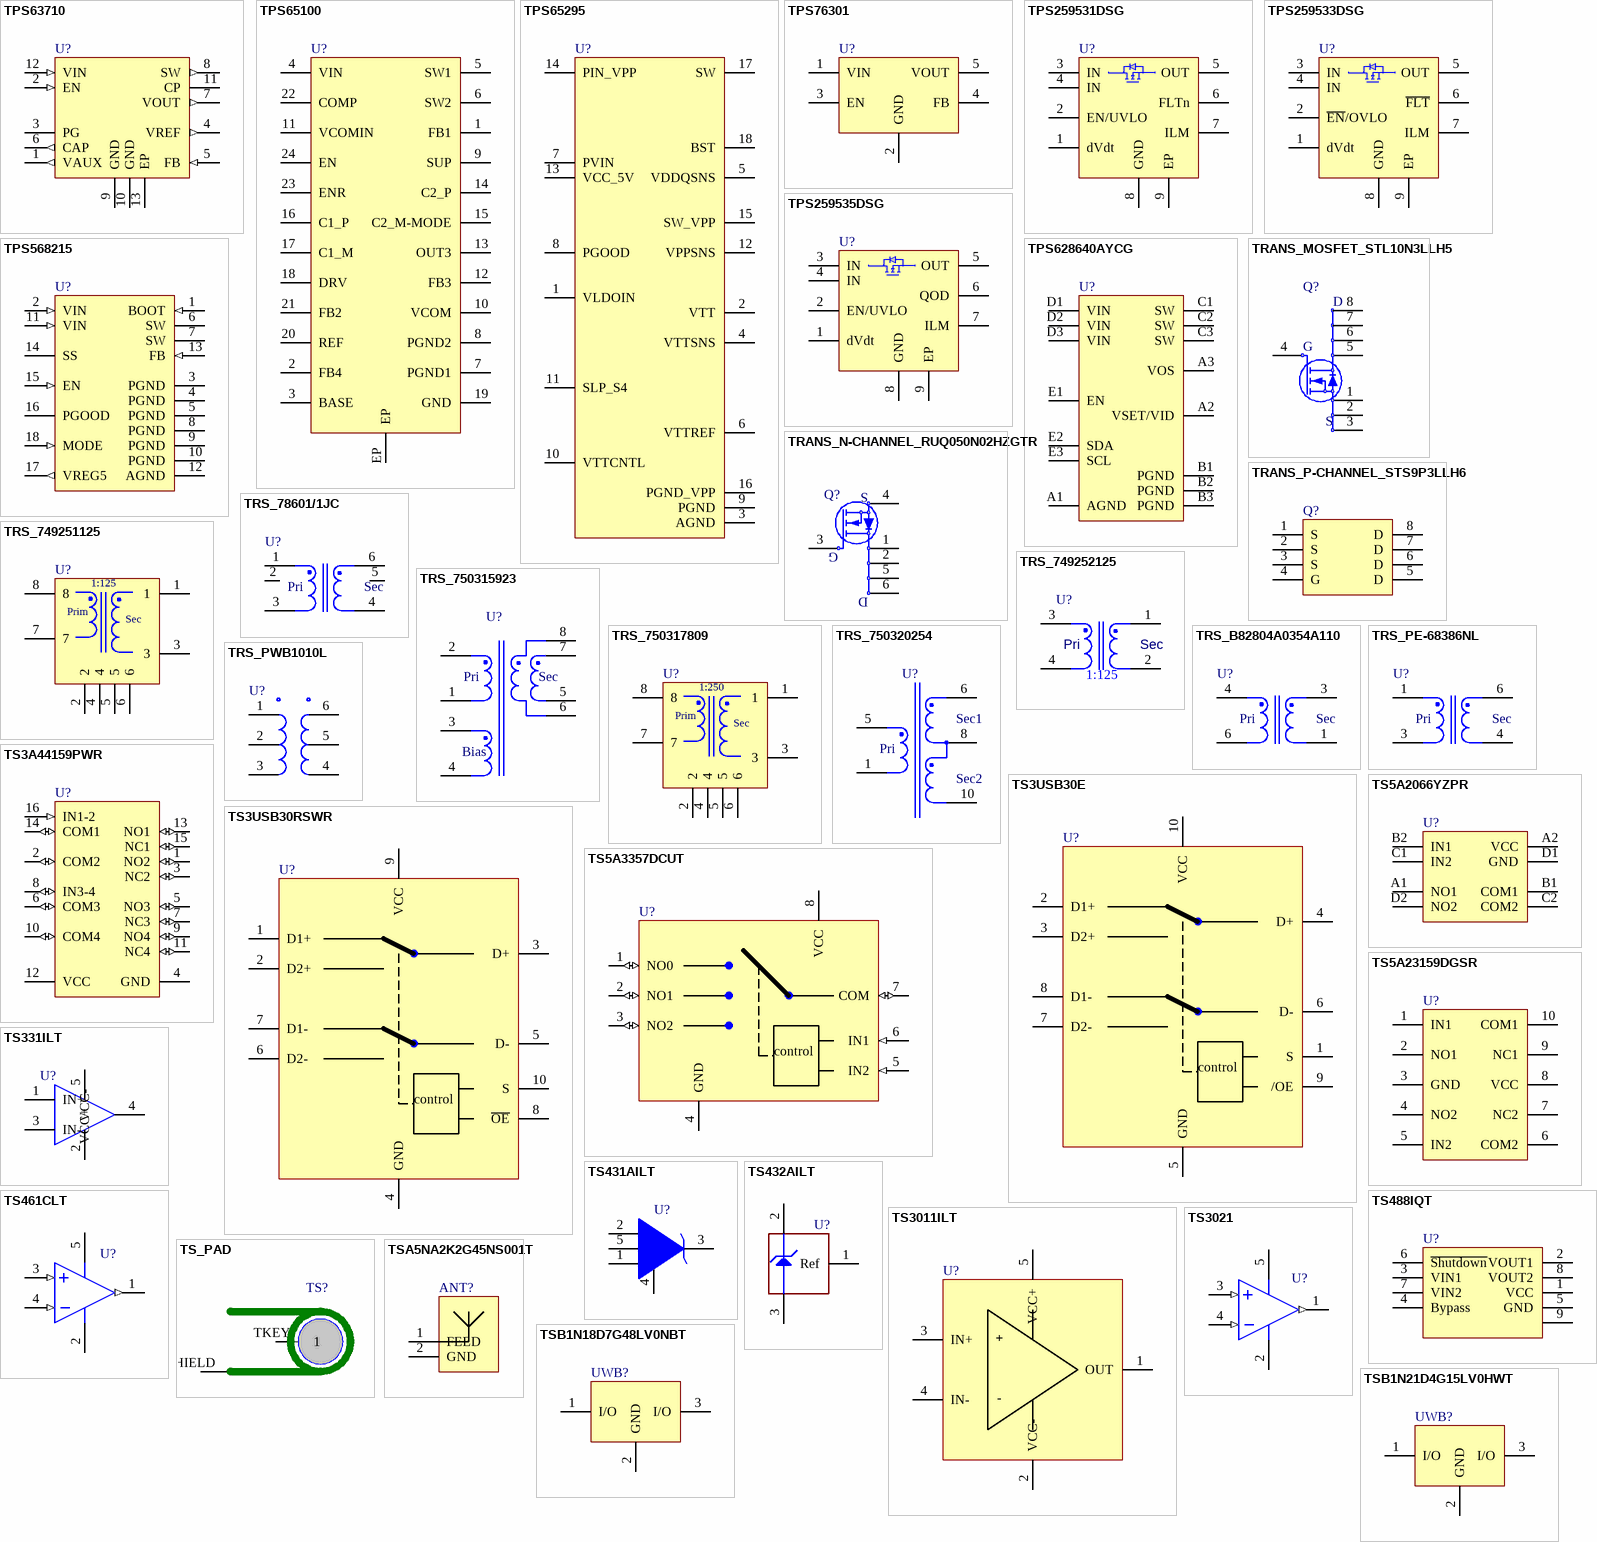
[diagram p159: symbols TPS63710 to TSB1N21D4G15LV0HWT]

## TPS63710
designator U?
pins: 1 VAUX (out), 2 EN (in), 3 PG (oc), 4 VREF (out), 5 FB (in), 6 CAP (out), 7 VOUT (out), 8 SW (out), 9 GND, 10 GND, 11 CP, 12 VIN (in), 13 EP

## TPS65100
designator U?
pins: 1 FB1, 2 FB4, 3 BASE, 4 VIN, 5 SW1, 6 SW2, 7 PGND1, 8 PGND2, 9 SUP, 10 VCOM, 11 VCOMIN, 12 FB3, 13 OUT3, 14 C2_P, 15 C2_M-MODE, 16 C1_P, 17 C1_M, 18 DRV, 19 GND, 20 REF, 21 FB2, 22 COMP, 23 ENR, 24 EN, EP

## TPS65295
designator U?
pins: 1 VLDOIN, 2 VTT, 3 AGND, 4 VTTSNS, 5 VDDQSNS, 6 VTTREF, 7 PVIN, 8 PGOOD, 9 PGND, 10 VTTCNTL, 11 SLP_S4, 12 VPPSNS, 13 VCC_5V, 14 PIN_VPP, 15 SW_VPP, 16 PGND_VPP, 17 SW, 18 BST

## TPS76301
designator U?
pins: 1 VIN, 2 GND, 3 EN, 4 FB, 5 VOUT

## TPS259531DSG
designator U?
pins: 1 dVdt, 2 EN/UVLO, 3 IN, 4 IN, 5 OUT, 6 FLTn, 7 ILM, 8 GND, 9 EP

## TPS259533DSG
designator U?
pins: 1 dVdt, 2 ~{EN}/OVLO, 3 IN, 4 IN, 5 OUT, 6 ~{FLT}, 7 ILM, 8 GND, 9 EP

## TPS259535DSG
designator U?
pins: 1 dVdt, 2 EN/UVLO, 3 IN, 4 IN, 5 OUT, 6 QOD, 7 ILM, 8 GND, 9 EP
